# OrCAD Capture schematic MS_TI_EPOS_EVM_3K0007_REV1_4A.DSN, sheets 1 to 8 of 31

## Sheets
1 Pg24: PLAT Test: size C; title: TMDXEVM438X; rev: 1.4A; company: Texas Instruments; note: am438x_ePOS_EVM_3k0007_rev1_4a.dsn; note: ARM MPU BU; note: Final
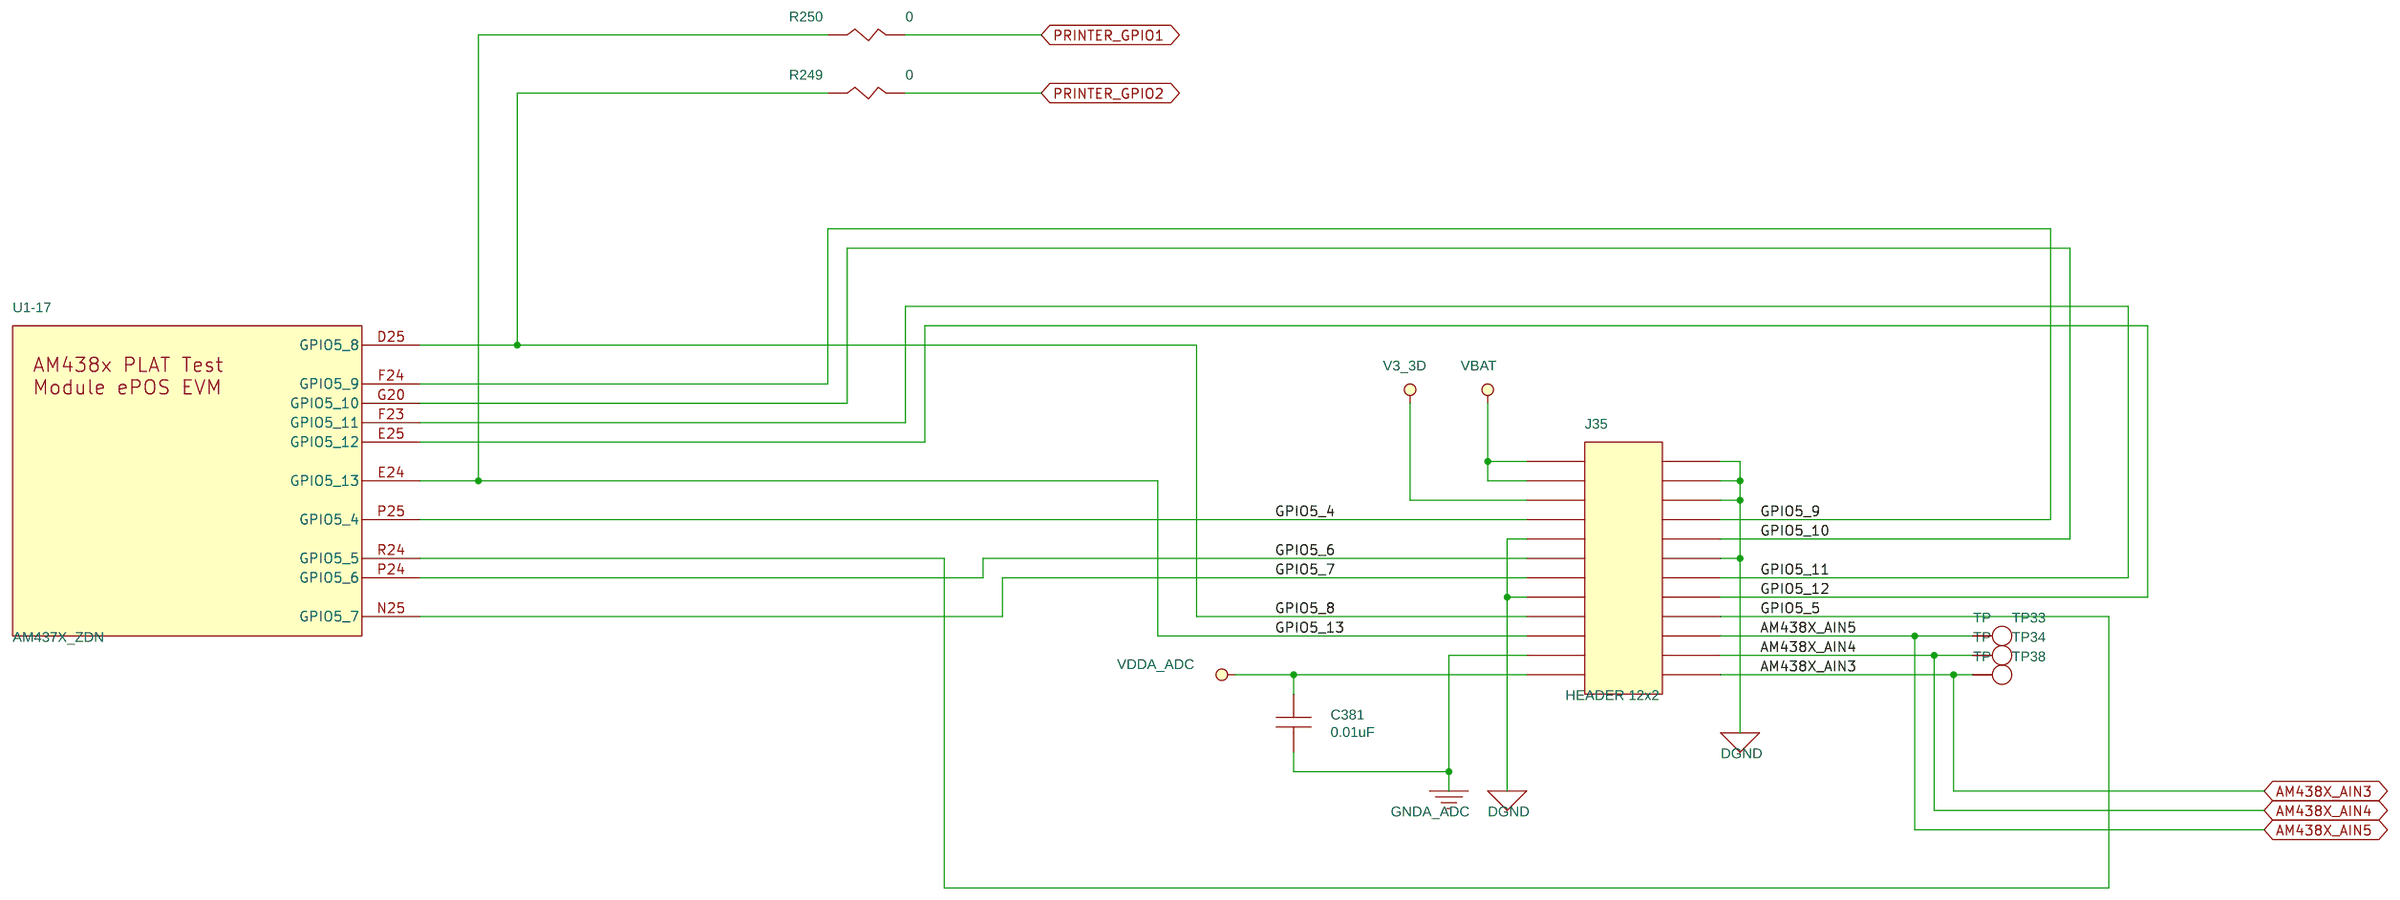
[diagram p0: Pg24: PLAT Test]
2 Pg15: Audio: size C
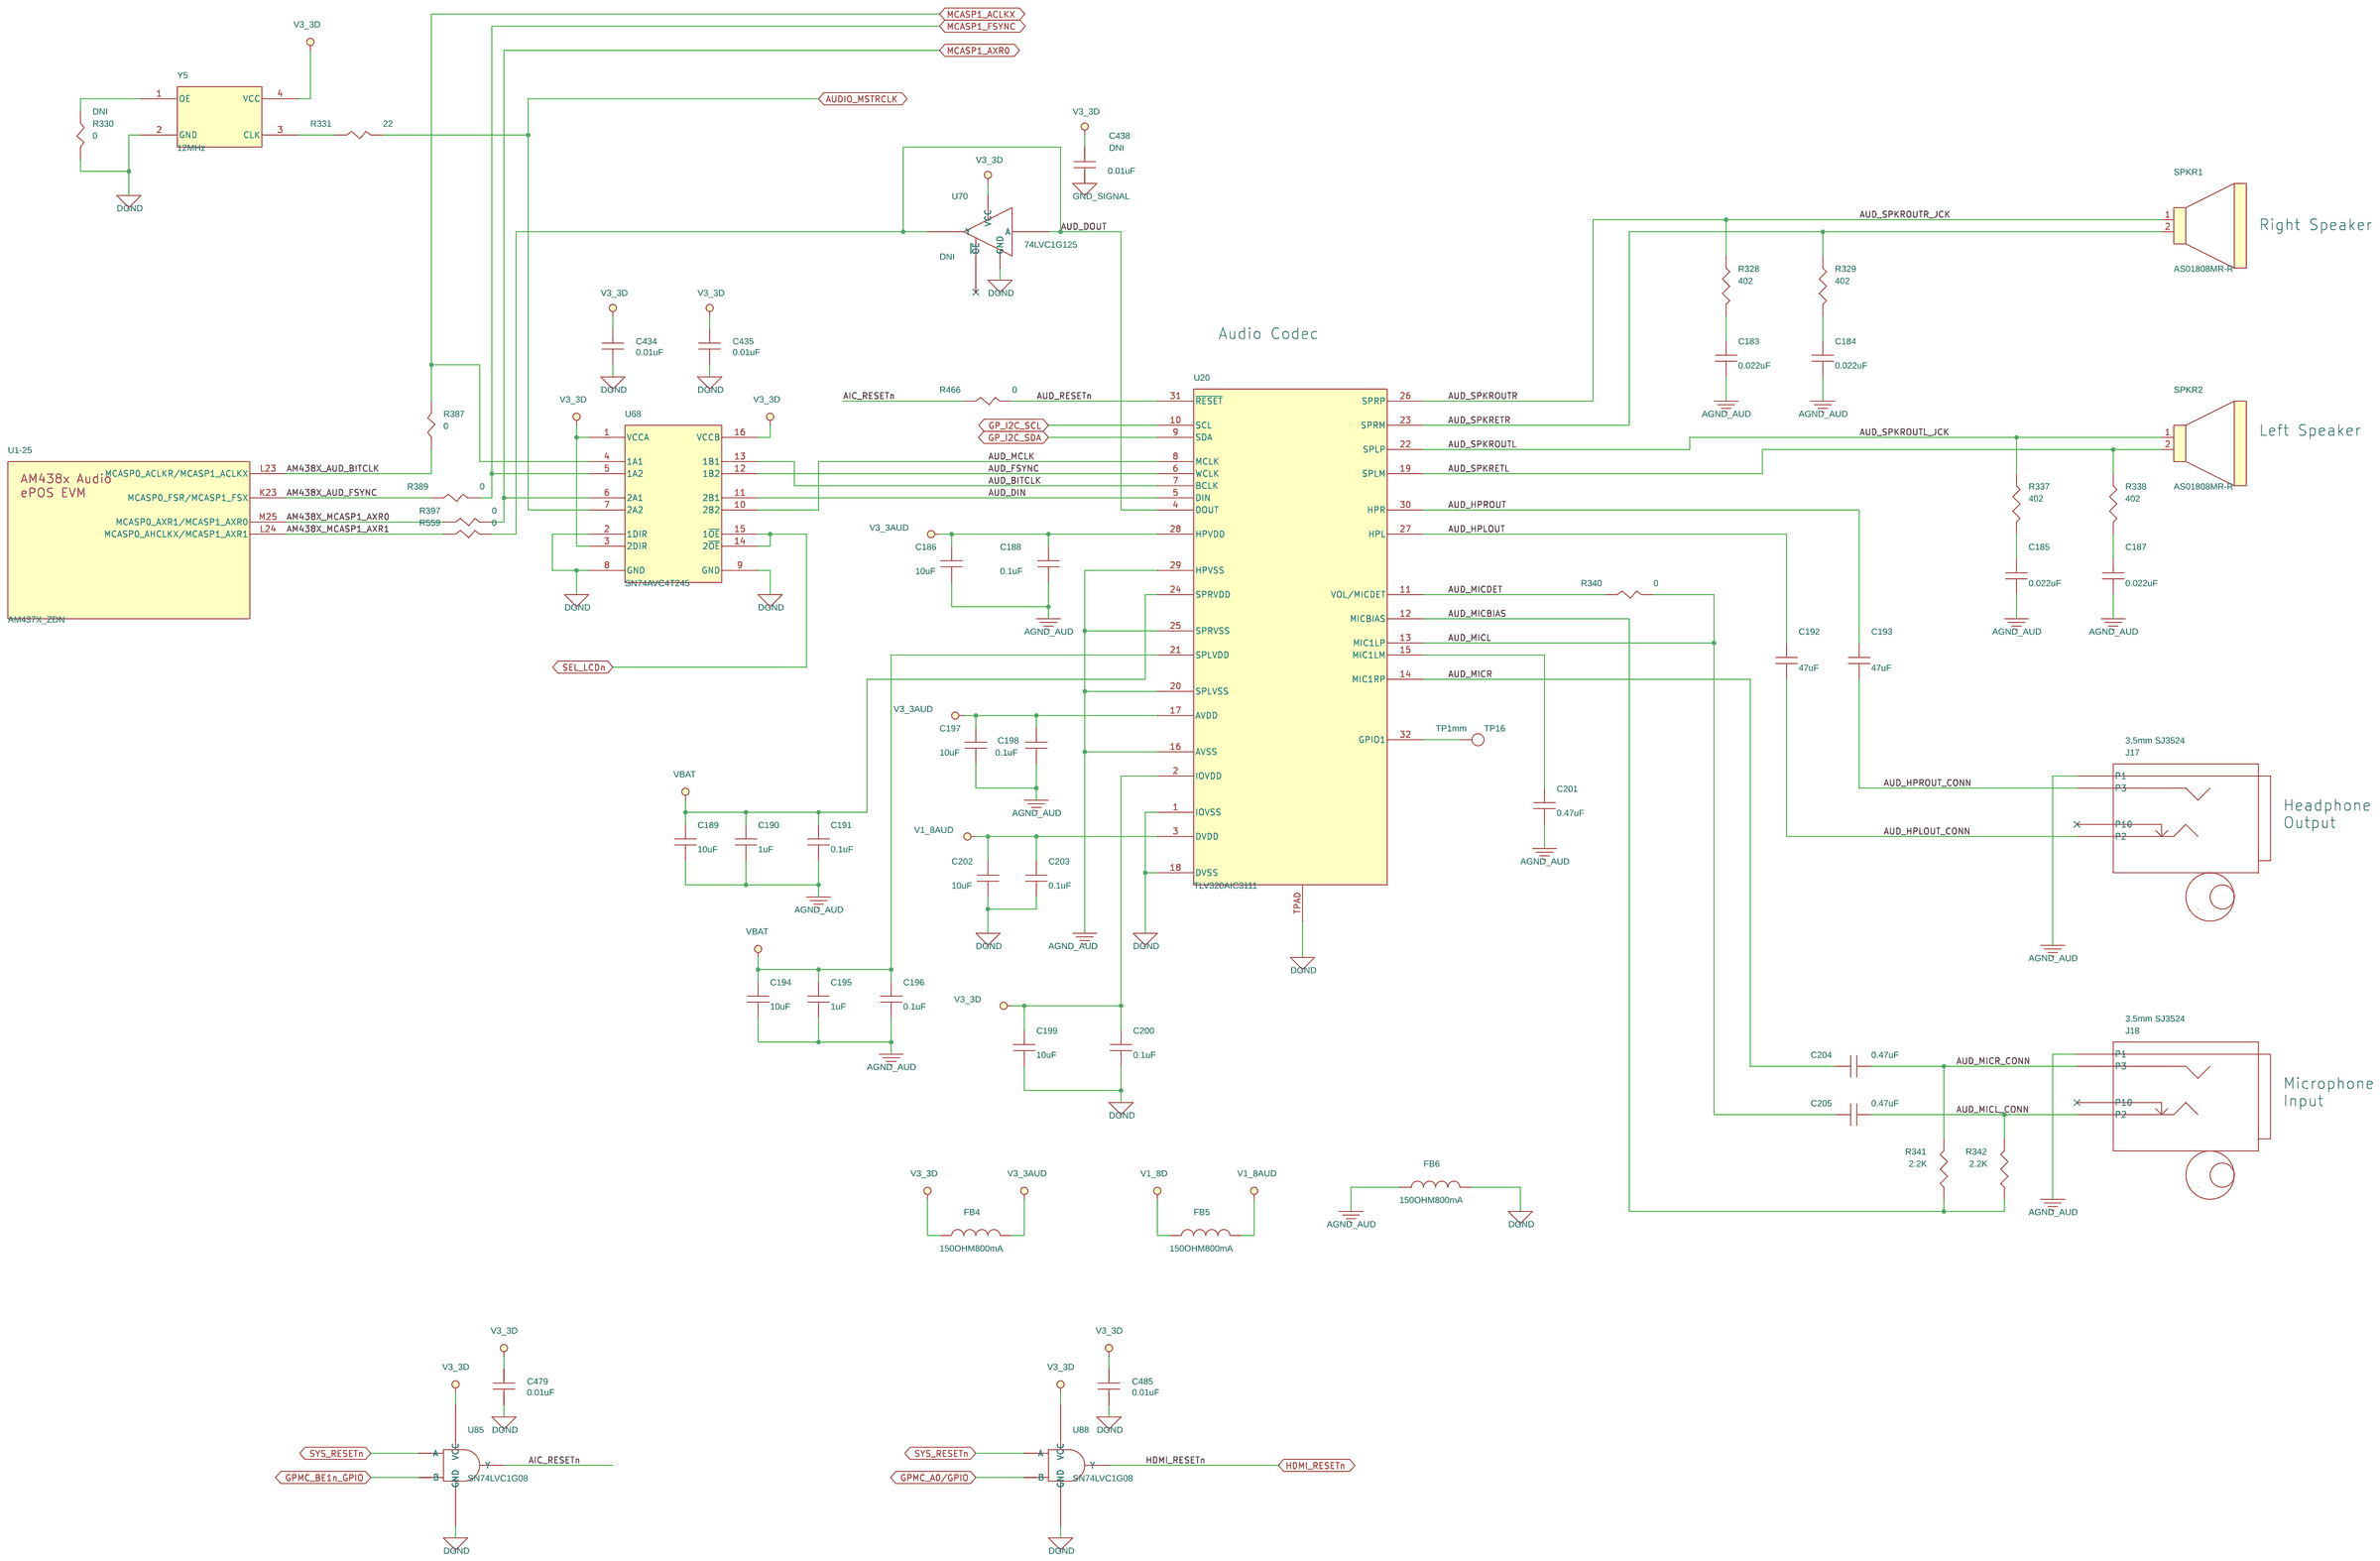
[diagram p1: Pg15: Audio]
3 Pg27: ADC: size C
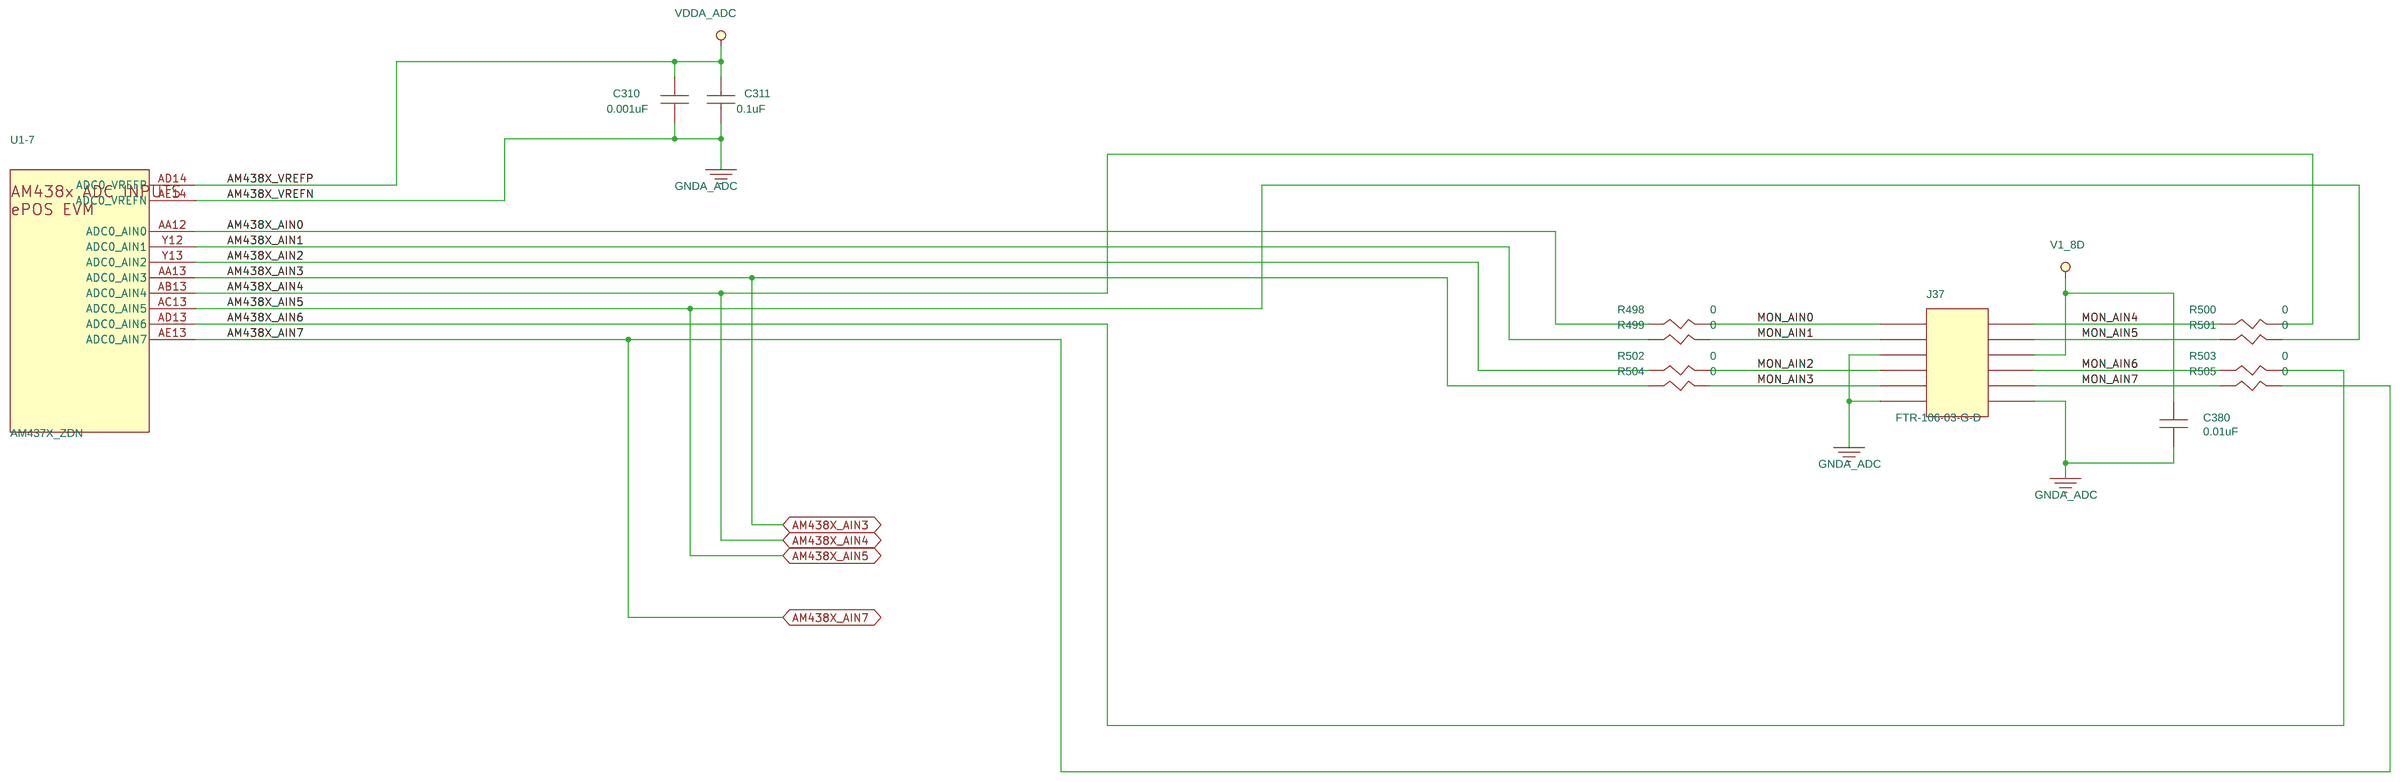
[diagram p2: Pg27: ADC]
4 Pg12: LCD: size C
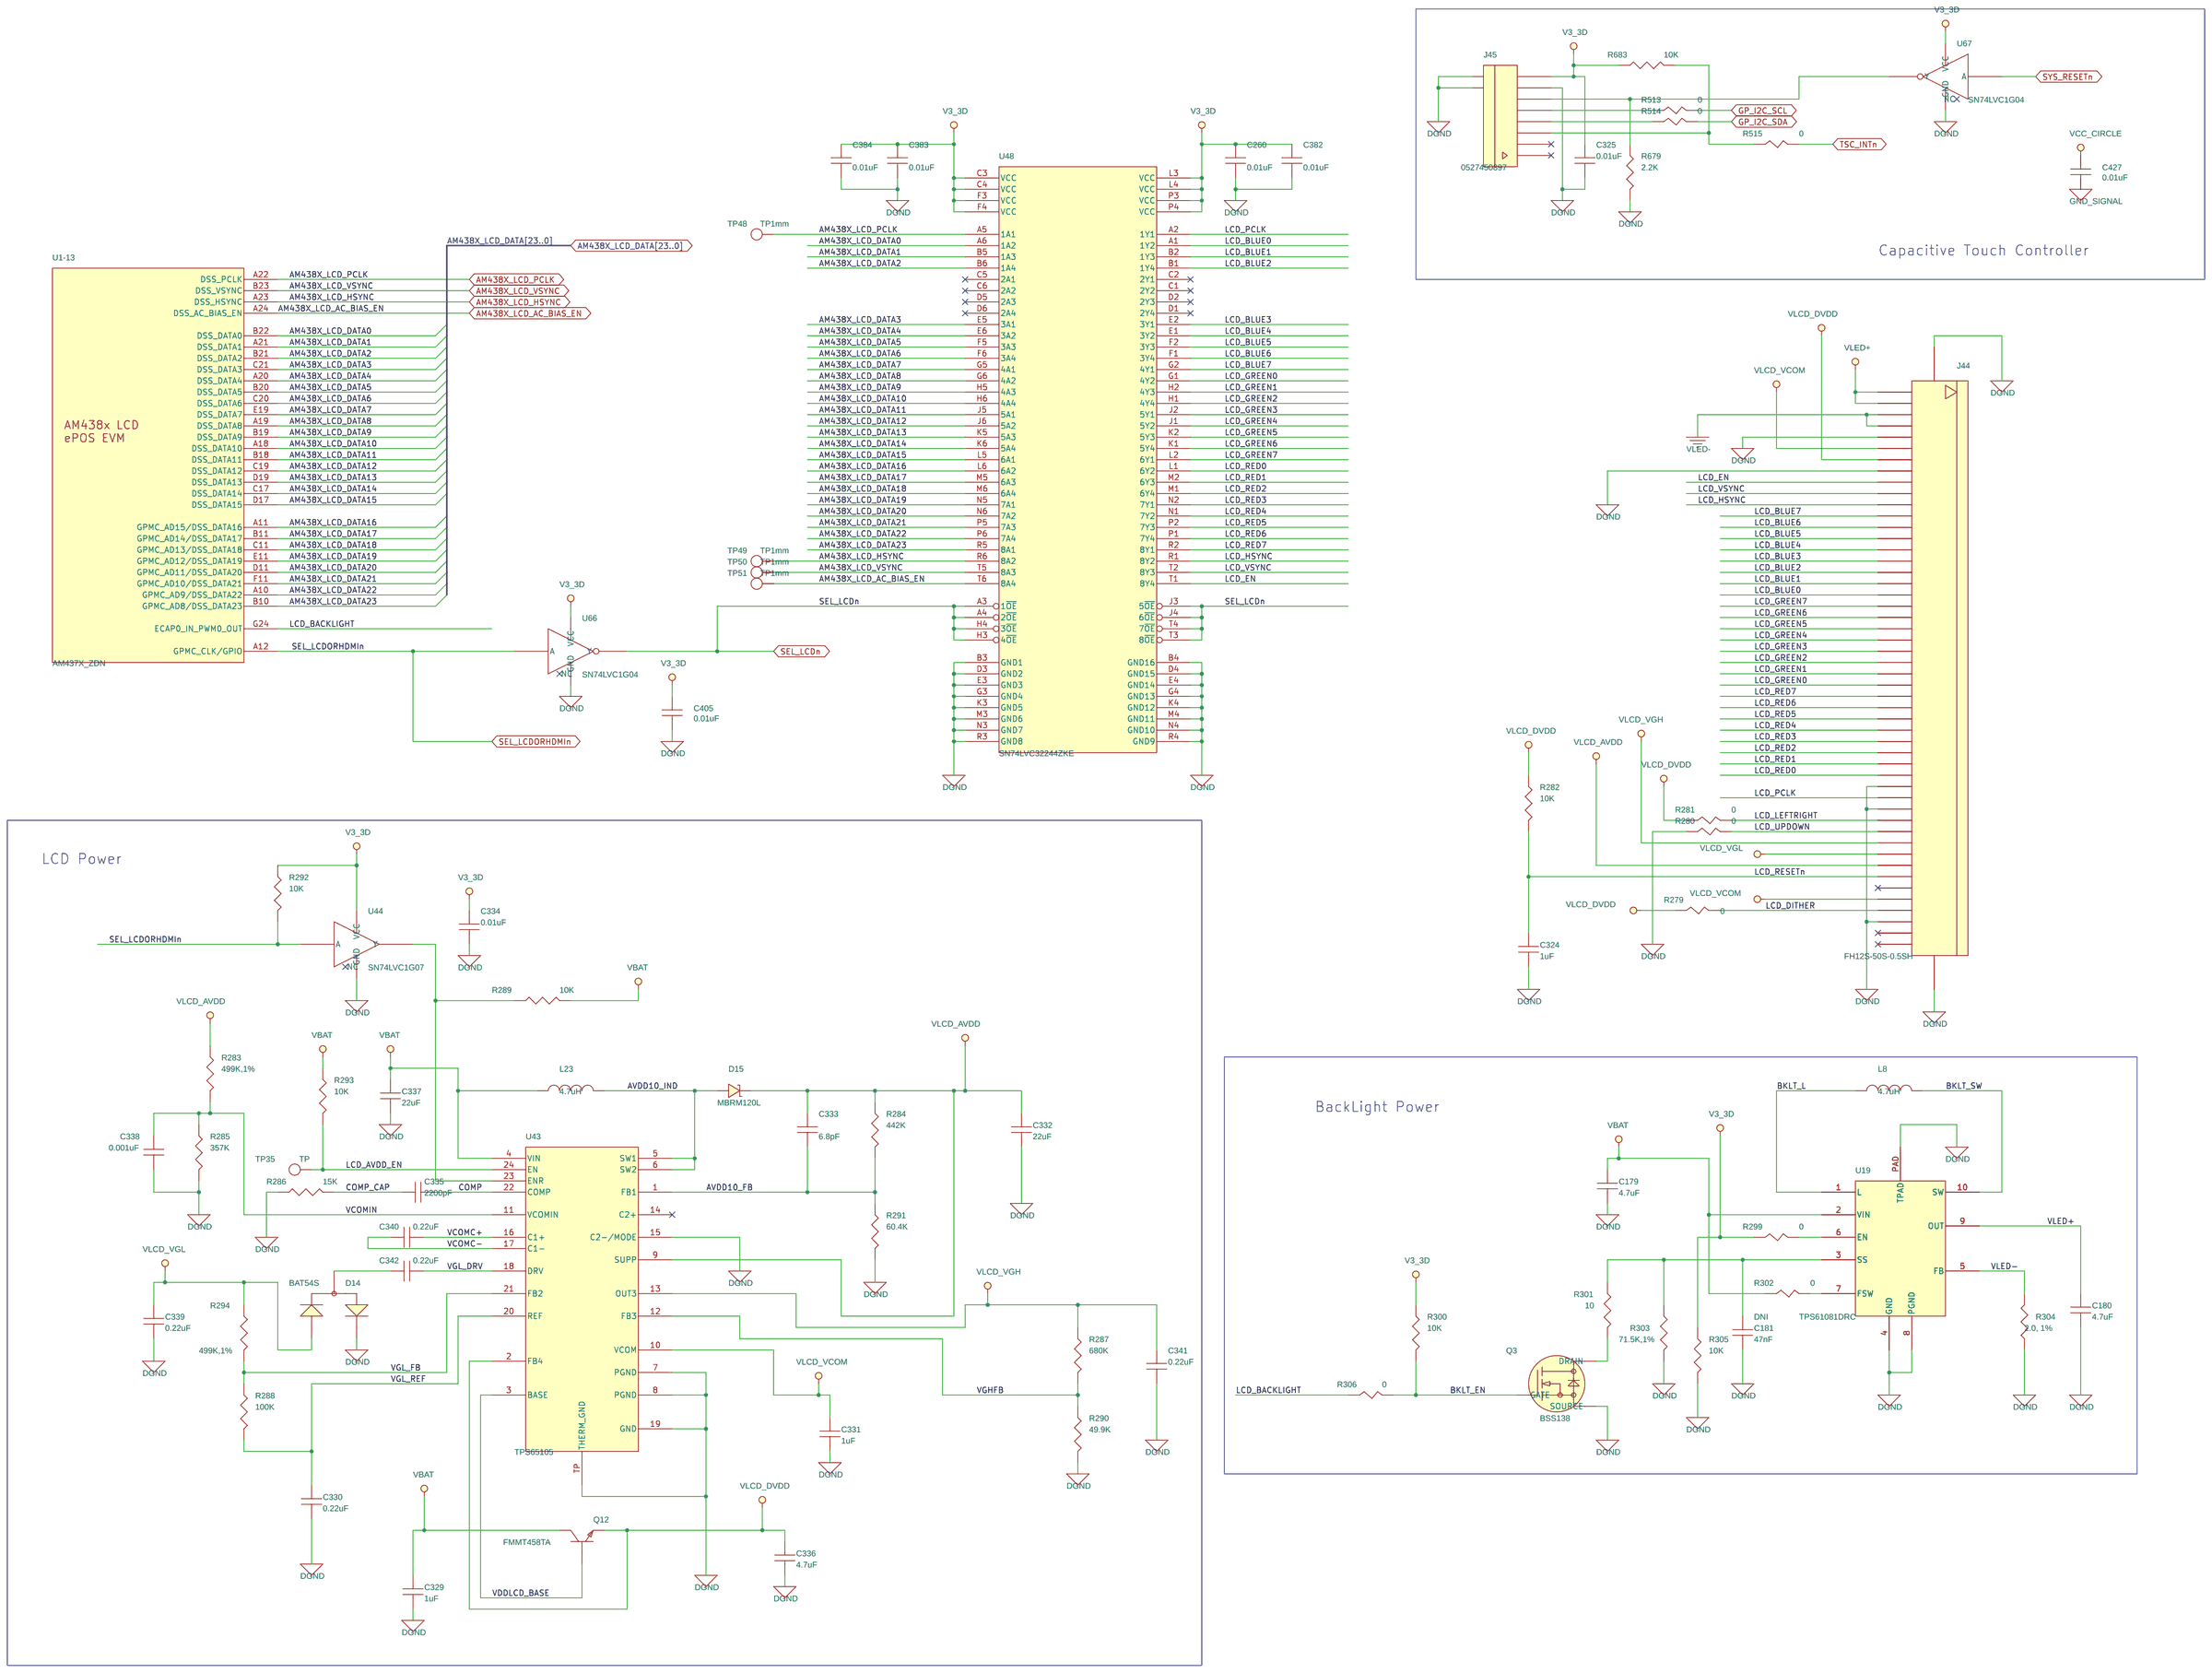
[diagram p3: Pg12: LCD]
5 Pg14: HDMI: size C
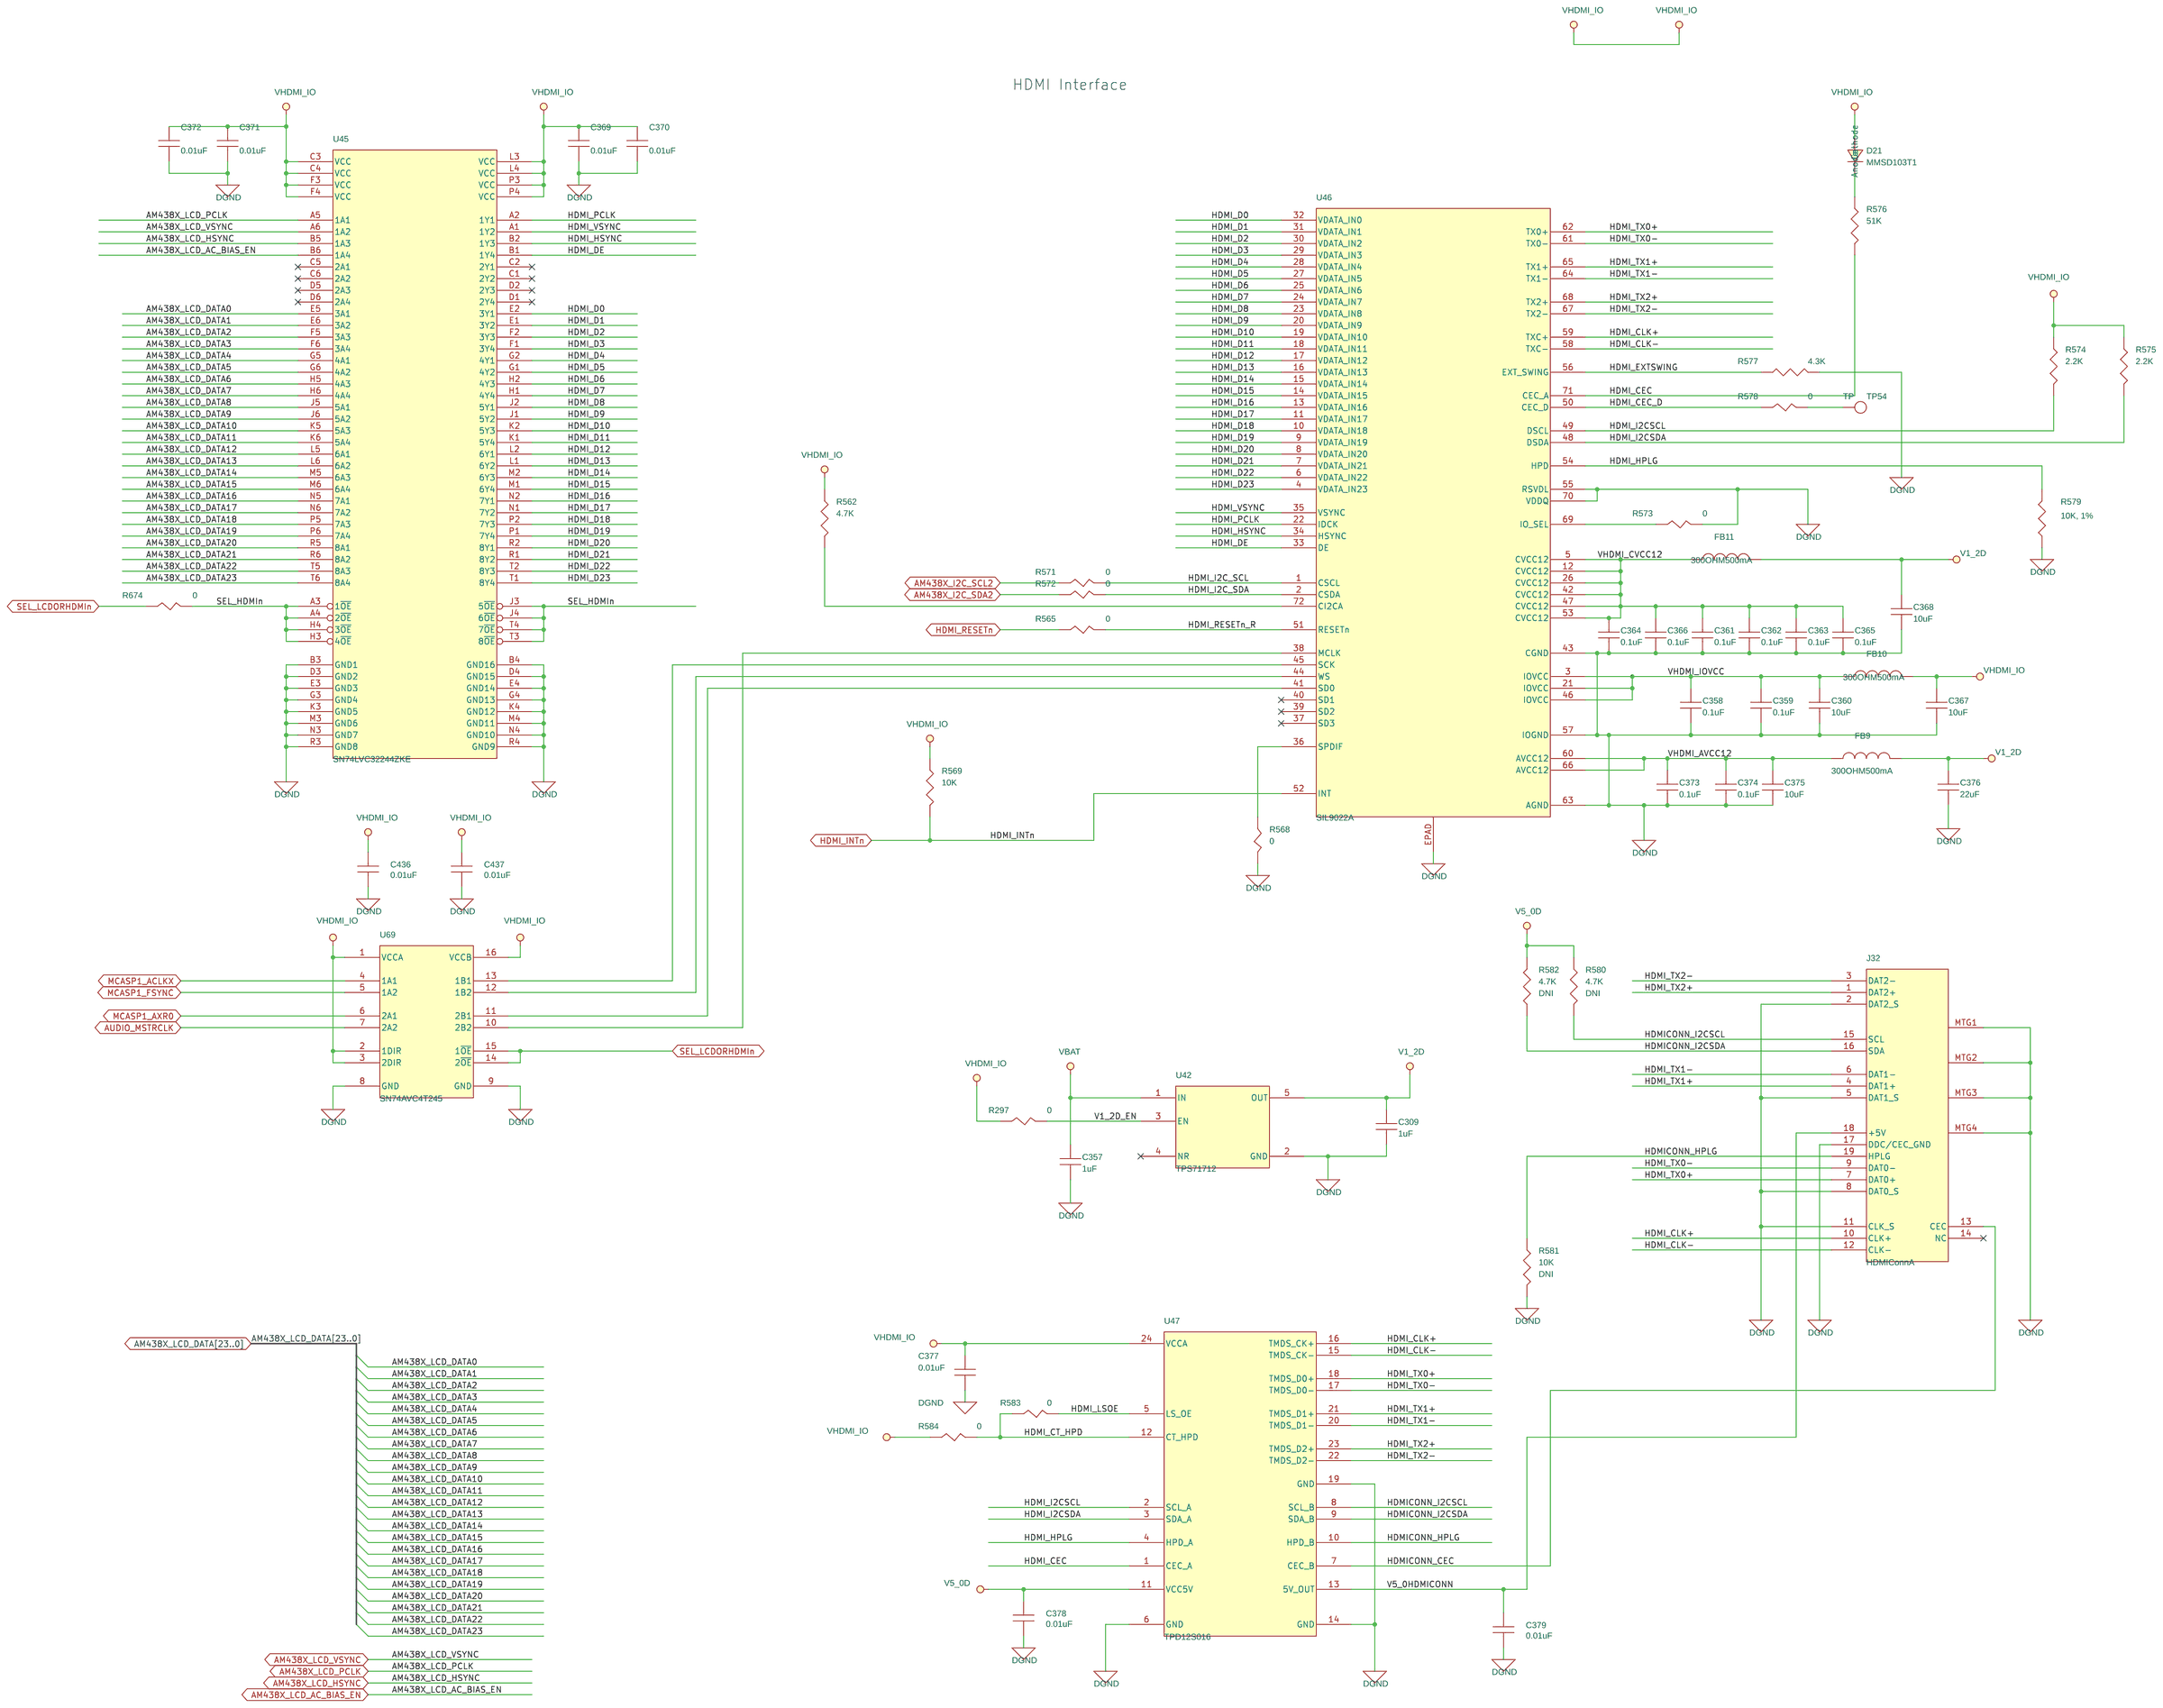
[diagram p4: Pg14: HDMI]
6 Pg25: Mag ADC: size C
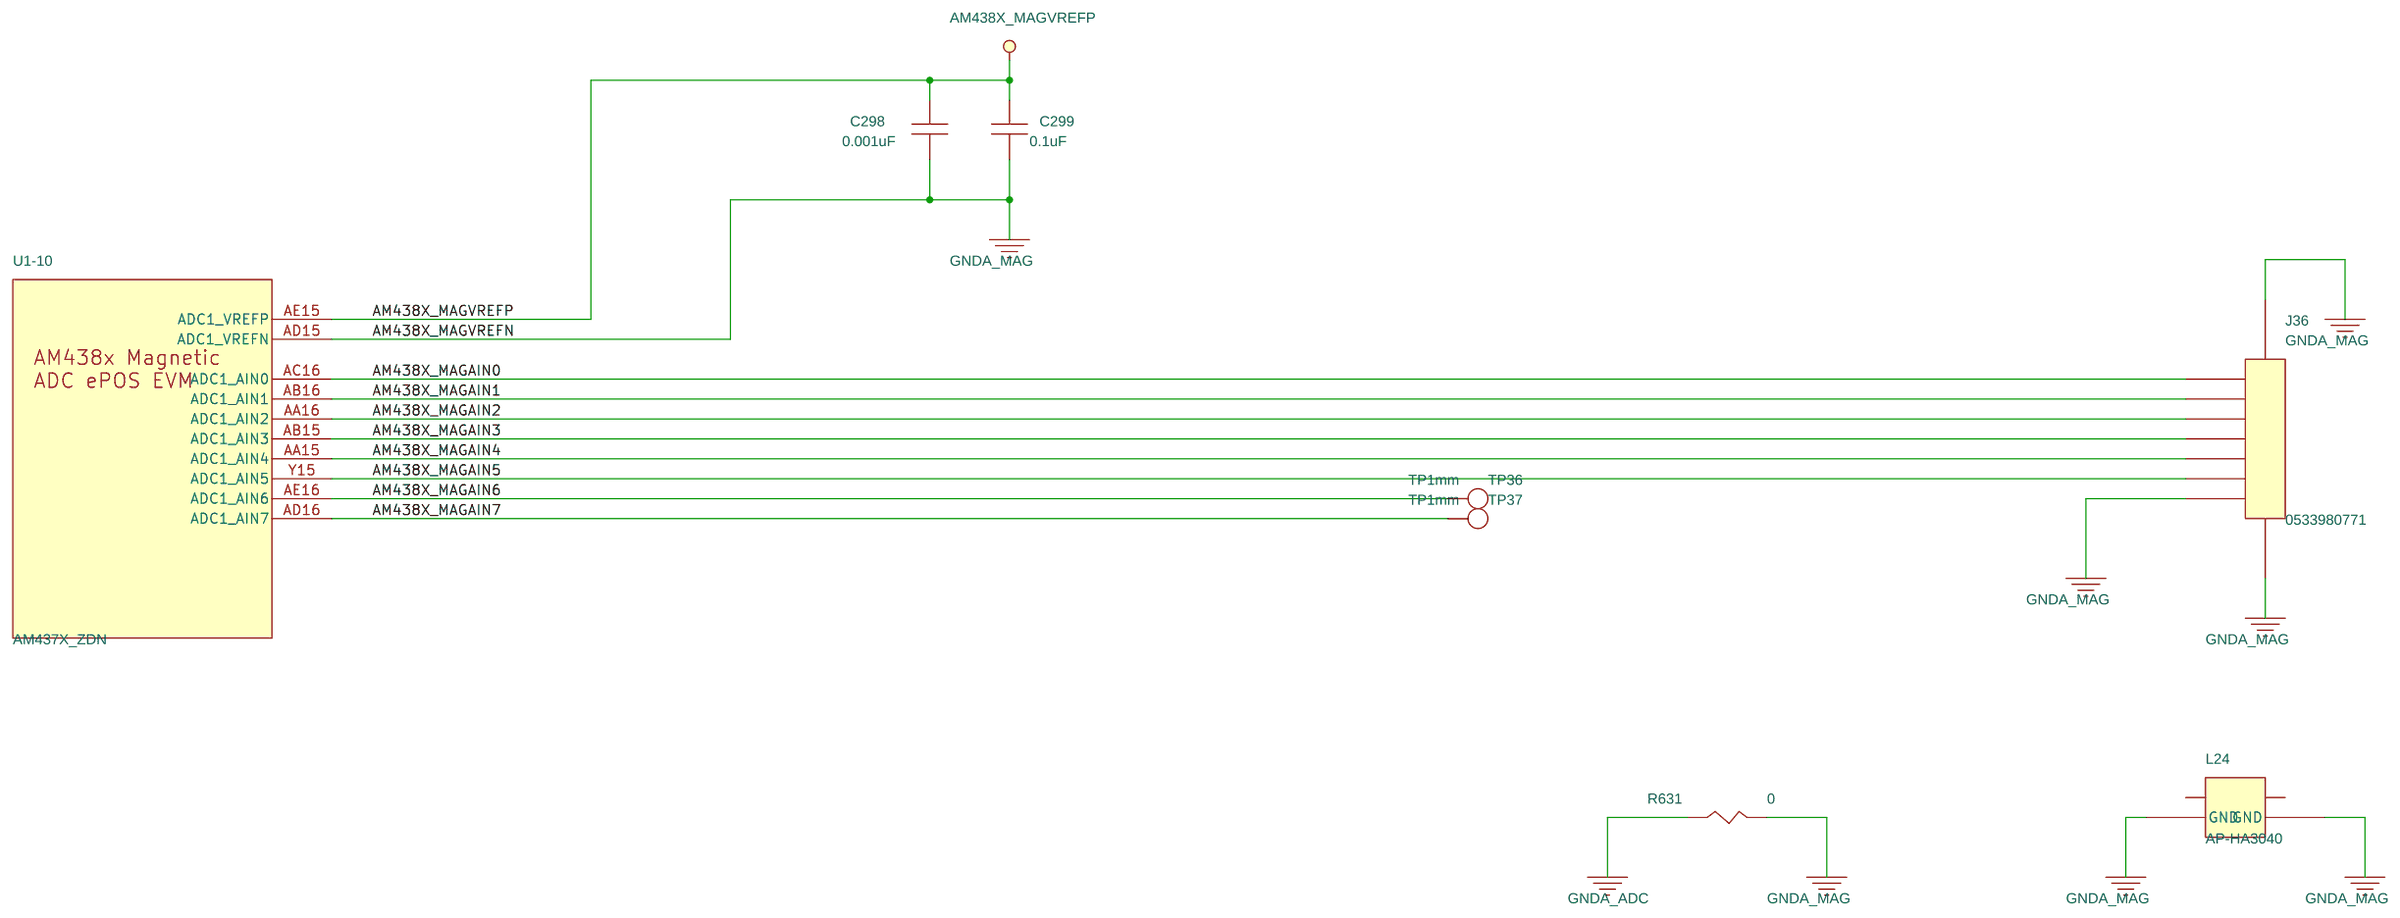
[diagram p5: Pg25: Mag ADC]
7 Pg13: Camera: size C
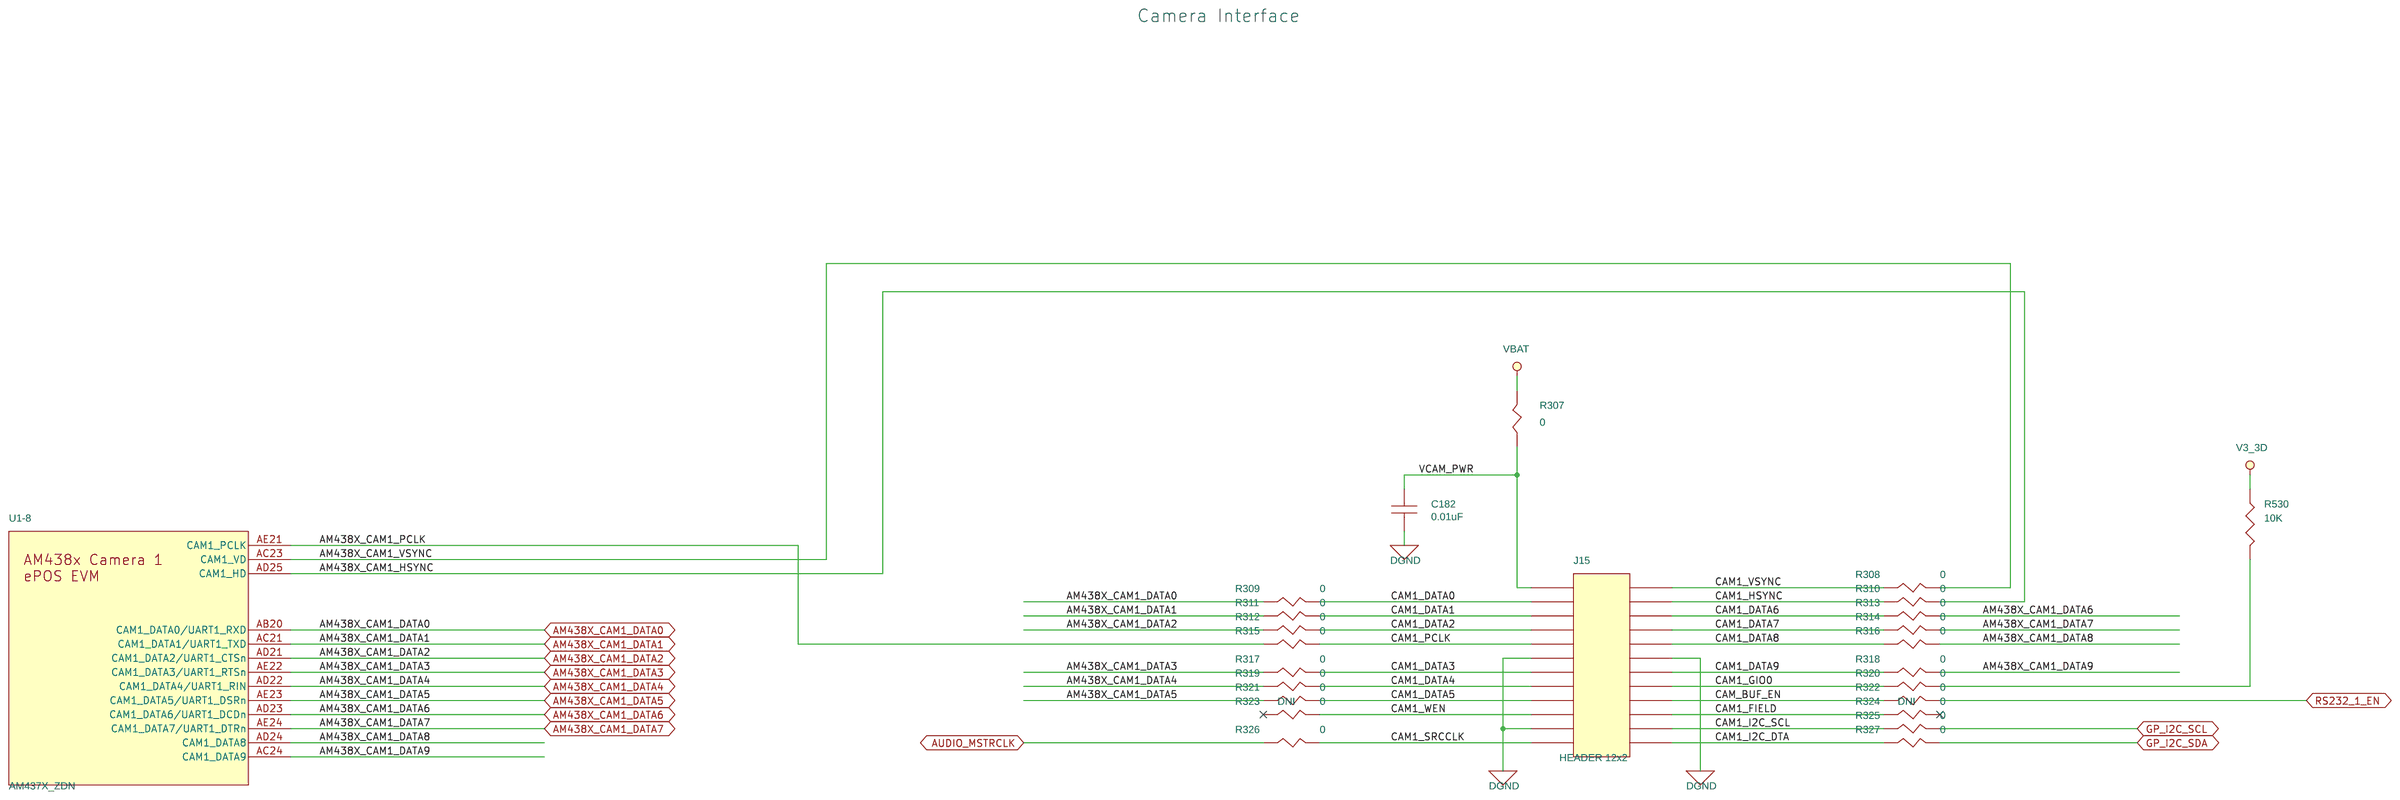
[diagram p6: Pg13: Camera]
8 Pg11: USB JTAG: size C
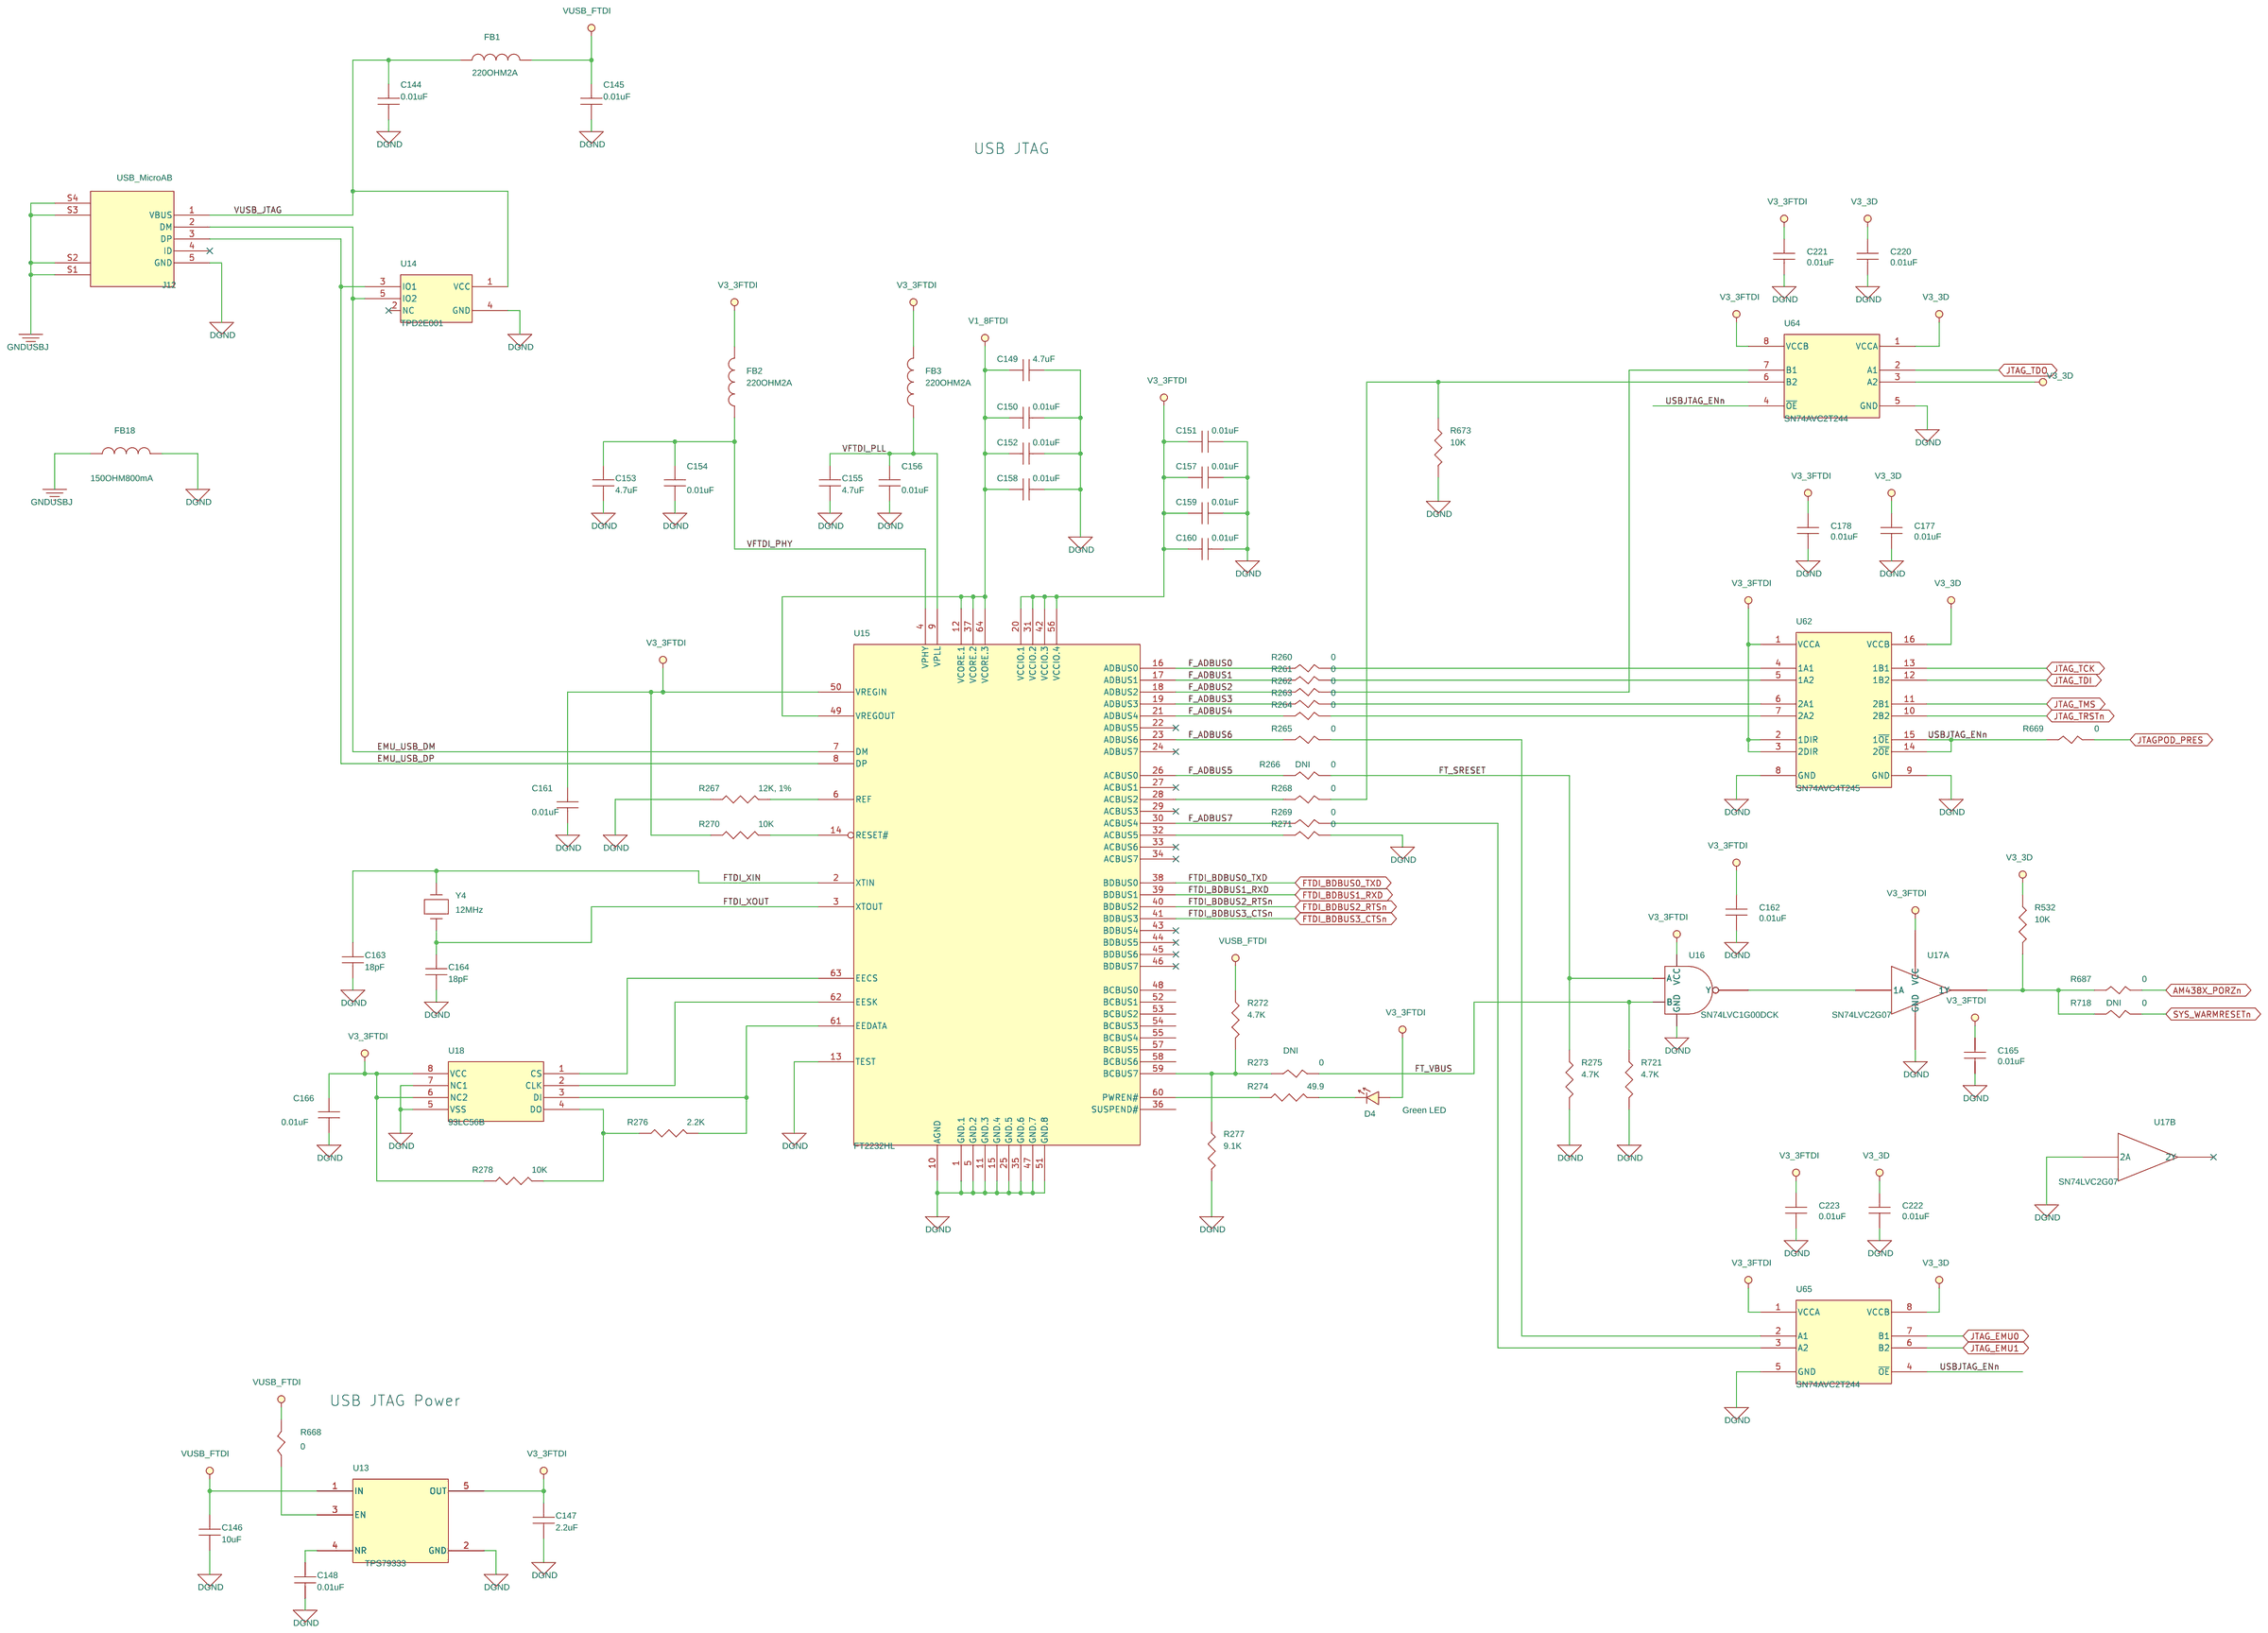
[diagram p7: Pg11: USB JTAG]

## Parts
sheet Pg11: USB JTAG
C144  0.01uF  [SM-7351-CAP-0402]
C145  0.01uF  [SM-7351-CAP-0402]
C146  10uF  [SM-7351-CAP-0805]
C147  2.2uF  [SM-7351-CAP-0805]
C148  0.01uF  [SM-7351-CAP-0402]
C149  4.7uF  [SM-7351-CAP-0603]
C150  0.01uF  [SM-7351-CAP-0402]
C151  0.01uF  [SM-7351-CAP-0402]
C152  0.01uF  [SM-7351-CAP-0402]
C153  4.7uF  [SM-7351-CAP-0603]
C154  0.01uF  [SM-7351-CAP-0402]
C155  4.7uF  [SM-7351-CAP-0603]
C156  0.01uF  [SM-7351-CAP-0402]
C157  0.01uF  [SM-7351-CAP-0402]
C158  0.01uF  [SM-7351-CAP-0402]
C159  0.01uF  [SM-7351-CAP-0402]
C160  0.01uF  [SM-7351-CAP-0402]
C161  0.01uF  [SM-7351-CAP-0402]
C162  0.01uF  [SM-7351-CAP-0402]
C163  18pF  [SM-7351-CAP-0402]
C164  18pF  [SM-7351-CAP-0402]
C165  0.01uF  [SM-7351-CAP-0402]
C166  0.01uF  [SM-7351-CAP-0402]
C177  0.01uF  [SM-7351-CAP-0402]
C178  0.01uF  [SM-7351-CAP-0402]
C220  0.01uF  [SM-7351-CAP-0402]
C221  0.01uF  [SM-7351-CAP-0402]
C222  0.01uF  [SM-7351-CAP-0402]
C223  0.01uF  [SM-7351-CAP-0402]
D4  Green LED  [sm_led_0805]
FB1  220OHM2A  [sm-7351-ind-0603]
FB2  220OHM2A  [sm-7351-ind-0603]
FB3  220OHM2A  [sm-7351-ind-0603]
FB18  150OHM800mA  [sm-7351-ind-0805]
J12  USB_MicroAB  [ZX62-AB-5PA]
R260  0  [SM-7351-RES-0402]
R261  0  [SM-7351-RES-0402]
R262  0  [SM-7351-RES-0402]
R263  0  [SM-7351-RES-0402]
R264  0  [SM-7351-RES-0402]
R265  0  [SM-7351-RES-0402]
R266  0  [SM-7351-RES-0402]
R267  12K, 1%  [SM-7351-RES-0402]
R268  0  [SM-7351-RES-0402]
R269  0  [SM-7351-RES-0402]
R270  10K  [SM-7351-RES-0402]
R271  0  [SM-7351-RES-0402]
R272  4.7K  [SM-7351-RES-0402]
R273  0  [SM-7351-RES-0402]
R274  49.9  [SM-7351-RES-0402]
R275  4.7K  [SM-7351-RES-0402]
R276  2.2K  [sm-7351-res-0402]
R277  9.1K  [SM-7351-RES-0402]
R278  10K  [SM-7351-RES-0402]
R532  10K  [SM-7351-RES-0402]
R668  0  [SM-7351-RES-0402]
R669  0  [SM-7351-RES-0402]
R673  10K  [SM-7351-RES-0402]
R687  0  [SM-7351-RES-0402]
R718  0  [SM-7351-RES-0402]
R721  4.7K  [SM-7351-RES-0402]
U13  TPS79333  [U_5_DBV]
U14  TPD2E001  [U_5_DRL]
U15  FT2232HL  [LQFP64pin]
U16  SN74LVC1G00DCK  [SC70-5-43M]
U17  SN74LVC2G07  [U_6_DCK]  (sections A,B)
U18  93LC56B  [SOIC8_MC]
U62  SN74AVC4T245  [U_16_PW]
U64  SN74AVC2T244  [son2x1-8-16m]
U65  SN74AVC2T244  [son2x1-8-16m]
Y4  12MHz  [SM_OSC_ABM3]
sheet Pg12: LCD
C179  4.7uF  [SM-7351-CAP-0603]
C180  4.7uF  [SM-7351-CAP-0603]
C181  47nF  [SM-7351-CAP-0402]
C260  0.01uF  [SM-7351-CAP-0402]
C324  1uF  [SM-7351-CAP-0402]
C325  0.01uF  [SM-7351-CAP-0402]
C329  1uF  [SM-7351-CAP-0402]
C330  0.22uF  [SM-7351-CAP-0603]
C331  1uF  [SM-7351-CAP-0402]
C332  22uF  [SM-7351-CAP-0805]
C333  6.8pF  [SM-7351-CAP-0402]
C334  0.01uF  [SM-7351-CAP-0402]
C335  2200pF  [SM-7351-CAP-0402]
C336  4.7uF  [SM-7351-CAP-0603]
C337  22uF  [SM-7351-CAP-0805]
C338  0.001uF  [SM-7351-CAP-0402]
C339  0.22uF  [SM-7351-CAP-0603]
C340  0.22uF  [SM-7351-CAP-0603]
C341  0.22uF  [SM-7351-CAP-0603]
C342  0.22uF  [SM-7351-CAP-0603]
C382  0.01uF  [SM-7351-CAP-0402]
C383  0.01uF  [SM-7351-CAP-0402]
C384  0.01uF  [SM-7351-CAP-0402]
C405  0.01uF  [SM-7351-CAP-0402]
C427  0.01uF  [SM-7351-CAP-0402]
D14  BAT54S  [SM_SOT323-3]
D15  MBRM120L  [SM_DIO_CASE_457-04]
J44  FH12S-50S-0.5SH  [cnfh12s-50s-05sh]
J45  0527450897  [CN527450-897]
L8  4.7uH  [vlcf5020t]
L23  4.7uH  [sm_ind_lqh32cn]
Q3  BSS138  [SOT23-3]
Q12  FMMT458TA  [sm_sot23_bce]
R279  0  [SM-7351-RES-0402]
R280  0  [SM-7351-RES-0402]
R281  0  [SM-7351-RES-0402]
R282  10K  [SM-7351-RES-0402]
R283  499K,1%  [SM-7351-RES-0402]
R284  442K  [SM-7351-RES-0402]
R285  357K  [SM-7351-RES-0402]
R286  15K  [SM-7351-RES-0402]
R287  680K  [SM-7351-RES-0402]
R288  100K  [SM-7351-RES-0402]
R289  10K  [SM-7351-RES-0402]
R290  49.9K  [SM-7351-RES-0402]
R291  60.4K  [SM-7351-RES-0402]
R292  10K  [SM-7351-RES-0402]
R293  10K  [SM-7351-RES-0402]
R294  499K,1%  [SM-7351-RES-0402]
R299  0  [SM-7351-RES-0402]
R300  10K  [SM-7351-RES-0402]
R301  10  [SM-7351-RES-0402]
R302  0  [SM-7351-RES-0402]
R303  71.5K,1%  [SM-7351-RES-0402]
R304  2.0, 1%  [SM-7351-RES-0603]
R305  10K  [SM-7351-RES-0402]
R306  0  [SM-7351-RES-0402]
R513  0  [SM-7351-RES-0402]
R514  0  [SM-7351-RES-0402]
R515  0  [SM-7351-RES-0402]
R679  2.2K  [sm-7351-res-0402]
R683  10K  [SM-7351-RES-0402]
TP35  TP  [TH_TP_5002]
TP48  TP1mm  [tp_smd1mmcircle]
TP49  TP1mm  [tp_smd1mmcircle]
TP50  TP1mm  [tp_smd1mmcircle]
TP51  TP1mm  [tp_smd1mmcircle]
U19  TPS61081DRC  [u_10_drc]
U43  TPS65105  [u_24_pw]
U44  SN74LVC1G07  [SC70-5-43M]
U48  SN74LVC32244ZKE  [bga13x5-96]
U66  SN74LVC1G04  [SC70-5-43M]
U67  SN74LVC1G04  [SC70-5-43M]
sheet Pg13: Camera
C182  0.01uF  [SM-7351-CAP-0402]
J15  HEADER 12x2  [hdr2x12]
R307  0  [SM-7351-RES-0402]
R308  0  [SM-7351-RES-0402]
R309  0  [SM-7351-RES-0402]
R310  0  [SM-7351-RES-0402]
R311  0  [SM-7351-RES-0402]
R312  0  [SM-7351-RES-0402]
R313  0  [SM-7351-RES-0402]
R314  0  [SM-7351-RES-0402]
R315  0  [SM-7351-RES-0402]
R316  0  [SM-7351-RES-0402]
R317  0  [SM-7351-RES-0402]
R318  0  [SM-7351-RES-0402]
R319  0  [SM-7351-RES-0402]
R320  0  [SM-7351-RES-0402]
R321  0  [SM-7351-RES-0402]
R322  0  [SM-7351-RES-0402]
R323  0  [SM-7351-RES-0402]
R324  0  [SM-7351-RES-0402]
R325  0  [SM-7351-RES-0402]
R326  0  [SM-7351-RES-0402]
R327  0  [SM-7351-RES-0402]
R530  10K  [SM-7351-RES-0402]
sheet Pg14: HDMI
C309  1uF  [SM-7351-CAP-0402]
C357  1uF  [SM-7351-CAP-0402]
C358  0.1uF  [SM-7351-CAP-0402]
C359  0.1uF  [SM-7351-CAP-0402]
C360  10uF  [SM-7351-CAP-0805]
C361  0.1uF  [SM-7351-CAP-0402]
C362  0.1uF  [SM-7351-CAP-0402]
C363  0.1uF  [SM-7351-CAP-0402]
C364  0.1uF  [SM-7351-CAP-0402]
C365  0.1uF  [SM-7351-CAP-0402]
C366  0.1uF  [SM-7351-CAP-0402]
C367  10uF  [SM-7351-CAP-0805]
C368  10uF  [SM-7351-CAP-0805]
C369  0.01uF  [SM-7351-CAP-0402]
C370  0.01uF  [SM-7351-CAP-0402]
C371  0.01uF  [SM-7351-CAP-0402]
C372  0.01uF  [SM-7351-CAP-0402]
C373  0.1uF  [SM-7351-CAP-0402]
C374  0.1uF  [SM-7351-CAP-0402]
C375  10uF  [SM-7351-CAP-0805]
C376  22uF  [SM-7351-CAP-0805]
C377  0.01uF  [SM-7351-CAP-0402]
C378  0.01uF  [SM-7351-CAP-0402]
C379  0.01uF  [SM-7351-CAP-0402]
C436  0.01uF  [SM-7351-CAP-0402]
C437  0.01uF  [SM-7351-CAP-0402]
D21  MMSD103T1  [sod-123]
FB9  300OHM500mA  [sm-7351-ind-0603]
FB10  300OHM500mA  [sm-7351-ind-0603]
FB11  300OHM500mA  [sm-7351-ind-0603]
J32  HDMIConnA  [smd_hdmia_ra]
R297  0  [SM-7351-RES-0402]
R562  4.7K  [SM-7351-RES-0402]
R565  0  [SM-7351-RES-0402]
R568  0  [SM-7351-RES-0402]
R569  10K  [SM-7351-RES-0402]
R571  0  [SM-7351-RES-0402]
R572  0  [SM-7351-RES-0402]
R573  0  [SM-7351-RES-0402]
R574  2.2K  [sm-7351-res-0402]
R575  2.2K  [sm-7351-res-0402]
R576  51K  [SM-7351-RES-0402]
R577  4.3K  [SM-7351-RES-0402]
R578  0  [SM-7351-RES-0402]
R579  10K, 1%  [SM-7351-RES-0402]
R580  4.7K  [SM-7351-RES-0402]
R581  10K  [SM-7351-RES-0402]
R582  4.7K  [SM-7351-RES-0402]
R583  0  [SM-7351-RES-0402]
R584  0  [SM-7351-RES-0402]
R674  0  [SM-7351-RES-0402]
TP54  TP  [TH_TP_5002]
U42  TPS71712  [smdsc70-5]
U45  SN74LVC32244ZKE  [bga13x5-96]
U46  SIL9022A  [QFN_72]
U47  TPD12S016  [pw_24pin_tssop]
U69  SN74AVC4T245  [U_16_PW]
sheet Pg15: Audio
C183  0.022uF  [SM-7351-CAP-0402]
C184  0.022uF  [SM-7351-CAP-0402]
C185  0.022uF  [SM-7351-CAP-0402]
C186  10uF  [SM-7351-CAP-0805]
C187  0.022uF  [SM-7351-CAP-0402]
C188  0.1uF  [SM-7351-CAP-0402]
C189  10uF  [SM-7351-CAP-0805]
C190  1uF  [SM-7351-CAP-0603]
C191  0.1uF  [SM-7351-CAP-0402]
C192  47uF  [SM-7351-CAP-1206]
C193  47uF  [SM-7351-CAP-1206]
C194  10uF  [SM-7351-CAP-0805]
C195  1uF  [SM-7351-CAP-0603]
C196  0.1uF  [SM-7351-CAP-0402]
C197  10uF  [SM-7351-CAP-0805]
C198  0.1uF  [SM-7351-CAP-0402]
C199  10uF  [SM-7351-CAP-0805]
C200  0.1uF  [SM-7351-CAP-0402]
C201  0.47uF  [SM-7351-CAP-0402]
C202  10uF  [SM-7351-CAP-0805]
C203  0.1uF  [SM-7351-CAP-0402]
C204  0.47uF  [SM-7351-CAP-0402]
C205  0.47uF  [SM-7351-CAP-0402]
C434  0.01uF  [SM-7351-CAP-0402]
C435  0.01uF  [SM-7351-CAP-0402]
C438  0.01uF  [SM-7351-CAP-0402]
C479  0.01uF  [SM-7351-CAP-0402]
C485  0.01uF  [SM-7351-CAP-0402]
FB4  150OHM800mA  [sm-7351-ind-0805]
FB5  150OHM800mA  [sm-7351-ind-0805]
FB6  150OHM800mA  [sm-7351-ind-0805]
J17  3.5mm SJ3524  [sj3524smt4pin]
J18  3.5mm SJ3524  [sj3524smt4pin]
R328  402  [SM-7351-RES-0603]
R329  402  [SM-7351-RES-0603]
R330  0  [SM-7351-RES-0402]
R331  22  [SM-7351-RES-0402]
R337  402  [SM-7351-RES-0603]
R338  402  [SM-7351-RES-0603]
R340  0  [SM-7351-RES-0402]
R341  2.2K  [sm-7351-res-0402]
R342  2.2K  [sm-7351-res-0402]
R387  0  [SM-7351-RES-0402]
R389  0  [SM-7351-RES-0402]
R397  0  [SM-7351-RES-0402]
R466  0  [SM-7351-RES-0402]
R559  0  [SM-7351-RES-0402]
SPKR1  AS01808MR-R  [th_as01808mr-r_cust]
SPKR2  AS01808MR-R  [th_as01808mr-r_cust]
TP16  TP1mm  [tp_smd1mmcircle]
U20  TLV320AIC3111  [qfn5x5-32ti-39m]
U68  SN74AVC4T245  [U_16_PW]
U70  74LVC1G125  [U_5_DCK]
U85  SN74LVC1G08  [sm-so-sc70-5]
U88  SN74LVC1G08  [sm-so-sc70-5]
Y5  12MHz  [ecs_smd3_2x5mm]
sheet Pg24: PLAT Test
C381  0.01uF  [SM-7351-CAP-0402]
J35  HEADER 12x2  [hdr2x12]
R249  0  [SM-7351-RES-0402]
R250  0  [SM-7351-RES-0402]
TP33  TP  [TH_TP_5002]
TP34  TP  [TH_TP_5002]
TP38  TP  [TH_TP_5002]
sheet Pg25: Mag ADC
C298  0.001uF  [SM-7351-CAP-0402]
C299  0.1uF  [SM-7351-CAP-0402]
J36  0533980771  [CNSD-0533980771]
L24  AP-HA3040  [AP-HA3040-MSR]
R631  0  [SM-7351-RES-0402]
TP36  TP1mm  [tp_smd1mmcircle]
TP37  TP1mm  [tp_smd1mmcircle]
sheet Pg26: Keypad/LED's
U1  AM437X_ZDN  [AM437X_ZDN]  (sections -1,-10,-11,-12,-13,-14,-15,-16,-17,-18,-19,-2,-20,-21,-22,-23,-24,-25,-26,-27,-3,-4,-5,-6,-7,-8,-9)
sheet Pg27: ADC
C310  0.001uF  [SM-7351-CAP-0402]
C311  0.1uF  [SM-7351-CAP-0402]
C380  0.01uF  [SM-7351-CAP-0402]
J37  FTR-106-03-G-D  [ftr-106-53-g-d-06]
R498  0  [SM-7351-RES-0402]
R499  0  [SM-7351-RES-0402]
R500  0  [SM-7351-RES-0402]
R501  0  [SM-7351-RES-0402]
R502  0  [SM-7351-RES-0402]
R503  0  [SM-7351-RES-0402]
R504  0  [SM-7351-RES-0402]
R505  0  [SM-7351-RES-0402]

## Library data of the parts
C144 C145 C148 C150-C152 C154 C156-C162 C165 C166 C177 C178 C182 C220-C223 C260 C325 C334 C369-C372 C377-C384 C405 C427 C434-C437 C479 C485 = 1C_0.01uFCapacitor16V10%0402: Cost100: 0; Cost10K: 0.01; Mistral Part No: 120009030032-R
C146 C186 C189 C194 C197 C199 C202 C360 C367 C368 C375 = 1C_10uFCapacitor16V10%0805: Cost10K: 0.04; Mistral Part No: 120011040011-R
C147 = 1C_2.2uFCapacitor35V20%smd0805: Cost10K: 0.04; MfrNum: C2012X7R1V225M125AB; Mistral Part No: M120016080004
C149 C153 C155 C179 C180 C336 = 1C_4.7uFCapacitor16V10%0603: Cost100: 0.01; Cost10K: 0; Mistral Part No: 120011050004-R
C163 C164 = 1C_18pFCapacitor16V10%0402: Cost100: 0.02; Cost10K: 0; MfrNum: CGA2B2C0G1H180J050BA; Mistral Part No: 120014050009-R
D4 = 1F_LED_Green: Cost100: 0.08; Cost10K: 0.03; Mistral Part No: 130014050065-R
FB1-FB3 = 1L_FerriteBead_220ohm2A: Cost100: 0.06; Cost10K: 0.04; MfrNum: MPZ1608S221ATA00; Mistral Part No: 130009030553
FB4-FB6 FB18 = 1L_FerBead_180ohm200mA: Cost100: 0.06; Cost10K: 0.04; Mistral Part No: 130014050062-R
J12 = 2C_MicroUSBAB: MfrNum: ZX62-AB-5PA(31); Mistral Part No: 150010120015-R
R249 R250 R260-R265 R268 R269 R271 R279-R281 R297 R299 R302 R306-R322 R325-R327 R340 R387 R389 R397 R466 R498-R505 R513-R515 R559 R565 R568 R571-R573 R578 R583 R584 R631 R668 R669 R674 R687 = 1R_ZeroOhmResistor1_16W0402: Mistral Part No: 110014100008-R
R266 R273 R323 R324 R330 R718 = 1R_ZeroOhmResistor1_16W0402: Loading: DNI; Mistral Part No: 110014100008-R
R267 = 1R_12Kohm1_16W1%SMD0402: Cost10K: 0; Mistral Part No: M110016080004
R270 R278 R282 R289 R292 R293 R300 R305 R530 R532 R569 R673 R683 = 1R_10KOhmResistor1_16W0402: Cost10K: 0; Mistral Part No: 110011060003-R
R272 R275 R562 R721 = 1R_4.7KOhmResistor1_16W0402: Cost100: 0; Cost10K: 0.02; Mistral Part No: 110014060028-R
R274 = 1R_49.9OhmResistor1_16W0402: Cost100: 0.06; Cost10K: 0.06; Mistral Part No: 110014060026-R
R276 R341 R342 R574 R575 R679 = 1R_2.2KOhmResistor1_16W0402: Cost100: 0.05; Cost10K: 0; Mistral Part No: 110014060053-R
R277 = 1R_9.1KohmResistor1_16W1%0402: Cost100: 0.01; Cost10K: 0; DescriptiveText: RES SMD 9.1K OHM 1% 1/16W 0402; MfrNum: MCR01MRTF9101; Mistral Part No: M110016080005
U13 = 1A_TPS79333: MfrNum: TPS79333DBVR; Mistral Part No: 142015020002-R
U14 = 1A_TPD2E001DRL: MfrNum: TPD2E001DRLR; Mistral Part No: M130016080007
U15 = 1A_FT2232_2: Cost10K: 3.1; Mistral Part No: 143014050006-R
U16 = 1A_SN74LVC1G00DCK: MfrNum: SN74LVC1G00DCKR; Mistral Part No: 141010060014-R
U17 = 1A_SN74LVC2G07: MfrNum: SN74LVC2G07DCKR; PACKAGE: 1
U18 = 1A_93C56EEPROM2Kbit: Mistral Part No: 141114050005-R
U62 U68 U69 = 1A_SN74AVC4T245: MfrNum: SN74AVC4T245PWR; Mistral Part No: 141009030111-R
U64 U65 = 1A_SN74AVC2T244: MfrNum: SN74AVC2T244DQMR; Mistral Part No: 141016030002-R
Y4 = 1Y_Crystal12MHzABM3: Cost10K: 0.5; Mistral Part No: 130016020045-R
C181 = 47nFCapacitor16V10%0402: Cost10K: 0.04; Loading: DNI; Mistral Part No: 120009050001-R
C309 C324 C329 C331 C357 = 1C_1uFCapacitor10V10%0402: Cost100: 0.33; Cost10K: 0.2; Mistral Part No: 120014050010-R
C330 C339-C342 = 1C_0.22uFCapacitor50V10%0603: Cost100: 0.01; Cost10K: 0; Mistral Part No: 120011060009-R
C332 C337 C376 = 1C_22uFCapacitor16V10%0805: Mistral Part No: 120014060009-R
C333 = 1C_6.8pFCapacitor50V10%SMD0402: Cost10K: 0.05; Mistral Part No: 120010080029-R
C335 = 1C_2200pFCapacitor50V10%SMD0402: Cost10K: 0.05; Mistral Part No: 120014050012-R
C298 C310 C338 = 1C_0.001uFCapacitor50V5%0402: Cost100: 0.01; Cost10K: 0; Mistral Part No: 120011060017-R
D14 = Diode200mA30V_Schottky: Mistral Part No: 130011050032-R
D15 = 1E_Diode1A20V_Schottky: Cost10K: 0.27; Mistral Part No: 130009030213-P
J44 = 2C_Conn_FPC_0.5mmpitch_50posbot: DescriptiveText: 50 Position FFC, FPC Connector Contacts, Bottom 0.020" (0.50mm) Surface Mount, Right Angle; MfrNum: FH12S-50S-0.5SH(55); Mistral Part No: 150016020021-R
J45 = 2C_Conn_FPC_527450897: Mistral Part No: 150014050029-R
L8 = 1L_4.7uHInductor30%1.7Asmd: Cost10K: 0.58; Mistral Part No: 130011050012-R
L23 = 1L_4.7uHInductor20%450mAsmd: Cost10K: 0.16; Mistral Part No: 130009060029-P
Q3 = 1Q_MOSFET_NChan_BSS138: Cost10K: 0.03; Mistral Part No: M130016080005
Q12 = 1Q_NPN_FMMT458: Mistral Part No: 130011040018-R
R283 R294 = 1R_499Kohm1_16W1%smd0402: Cost100: 0; Cost10K: 0.02; Mistral Part No: 110009090015-P
R284 = 1R_442Kohm1_16W1%smd0402: Cost100: 0; Cost10K: 0; Mistral Part No: 110014060041-R
R285 = 1R_357Kohm1_10W1%smd0402: Cost100: 0; Cost10K: 0; Mistral Part No: 110014060049-R
R286 = 1R_15Kohm1_16W1%smd0402: Cost100: 0; Cost10K: 0.02; Mistral Part No: 110014060042-R
R287 = 1R_680Kohm1_16W1%smd0402: Cost100: 0; Cost10K: 0.02; Mistral Part No: 110014060042-R
R288 = 1R_100KOhmResistor1_16W0402: Cost100: 0.01; Cost10K: 0; Mistral Part No: 110014060043-R
R290 = 1R_49.9KOhmResistor1_16W0402: Cost100: 0; Cost10K: 0.02; Mistral Part No: 110014060031-R
R291 = 1R_60.4Kohm1_16W1%smd0402: Cost100: 0; Cost10K: 0.02; Mistral Part No: 110014060047-R
R301 = 1R_10ohm1_16W5%smd0402: Cost10K: 0; Mistral Part No: 110014060037-R
R303 = 1R_71.5Kohm1_10W1%smd0402: Mistral Part No: 110009080026-R
R304 = 1R_2OhmResistor1_10W1%0603: Cost100: 0; Cost10K: 0.02; Mistral Part No: 110009110001-P
TP33-TP35 TP38 TP54 = 2H_TestPointThroughHole: Cost100: 0.16; Cost10K: 0.1; Mistral Part No: 160016120008-R
TP16 TP36 TP37 TP48-TP51 = 2H_Testpoint_SMD1mmCircle
U19 = 1A_TPS61081DRC: Cost10K: 0.5; MfrNum: TPS61081DRCR; Mistral Part No: 142009100003
U43 = 1A_TPS65105PWP: MfrNum: TPS65105PWPR; Mistral Part No: 142011050004-R
U44 = 1A_SN74LVC1G07: MfrNum: SN74LVC1G07DCKR; Mistral Part No: 141014060023-R
U45 U48 = 1A_SN74LVC32244: MfrNum: SN74LVC32244ZKER; Mistral Part No: 141014060009-R
U66 U67 = 1A_SN74LVC1G04: Cost10K: 0.23; MfrNum: SN74LVC1G04DCKR; Mistral Part No: 141009070007-R
J15 J35 = 2H_Header12x2: Cost10K: 0.57; Mistral Part No: 150014050022-R
C358 C359 C373 C374 = 1C_0.1uFCapacitor50V10%0402: Cost10K: 0.02; MfrNum: C1005X7R1H104K050BB; Mistral Part No: 120011100014-R
C188 C191 C196 C198 C200 C203 C299 C311 C361-C366 = 1C_0.1uFCapacitor16V10%0402: Cost10K: 0.01; MfrNum: C0402C104K4RACTU; Mistral Part No: 120009030060-R
D21 = Diode200mA250V: Mistral Part No: 130014060029-R
FB9-FB11 = 1L_FerriteBead_300ohm500mA: Cost100: 0.06; Cost10K: 0.04; MfrNum: MMZ1608R301ATA00; Mistral Part No: 130014060028-R
J32 = 2C_Conn_HDMI_TypeA: Mistral Part No: 150010050001
R576 = 1R_51Kohm1_16W1%smd0402: Cost100: 0.01; Cost10K: 0; Mistral Part No: 110014060030-R
R577 = 1R_4.3KOhmResistor1_16W0402: Cost100: 0; Cost10K: 0.02; Mistral Part No: 110014060029-R
R579 = 1R_10KOhmResistor1_10W1%0402: Cost100: 0.01; Cost10K: 0; Mistral Part No: 110015050015-R
R580 R582 = 1R_4.7KOhmResistor1_16W0402: Cost100: 0; Cost10K: 0.02; Loading: DNI; Mistral Part No: 110014060028-R
R581 = 1R_10KOhmResistor1_16W0402: Cost10K: 0; Loading: DNI; Mistral Part No: 110011060003-R
U42 = 1A_TPS71712: Cost10K: 4.7; MfrNum: TPS71712DCKR; Mistral Part No: 142014060014-R
U46 = 1A_SIL9022A: Cost100: 10; Cost10K: 1; Mistral Part No: M141016080004
U47 = 1A_TPD12S016: MfrNum: TPD12S016PWR; Mistral Part No: 141011080021
C183-C185 C187 = 1C_0.022uFCapacitor16Vsmd0402: Cost10K: 0.04; DescriptiveText: 0.022µF ±10% 50V Ceramic Capacitor X7R 0402; MfrNum: C1005X7R1H223K050BB; Mistral Part No: M120016080005; PartName: 0.022µF ±10% 50V Ceramic Capacitor X7R 0402
C190 C195 = 1C_1uFCapacitor50V10%0603: Cost10K: 0.04; Mistral Part No: M120016080002
C192 C193 = 1C_47uFCapacitor16V20%1206: MfrNum: C3216X5R1C476M160AB; Mistral Part No: 120011060001-R
C201 C204 C205 = 1C_0.47uFCapacitor16V10%0402: Cost10K: 0.02; Mistral Part No: 120009030119
C438 = 1C_0.01uFCapacitor16V10%0402: Cost100: 0; Cost10K: 0.01; Loading: DNI; Mistral Part No: 120009030032-R
J17 J18 = 2C_Conn_3.5mm_SJ3524SMT: Mistral Part No: M150016080004
R328 R329 R337 R338 = 1R_402ohm1_10W1%smd0603: Cost100: 0; Cost10K: 0.02; Mistral Part No: M110016080006
R331 = 1R_22OhmResistor1_16W1%0402: Cost100: 0.06; Cost10K: 0; DescriptiveText: RES SMD 22 OHM 1% 1/16W 0402; MfrNum: MCR01MRTF22R0; Mistral Part No: 110014060035-R
SPKR1 SPKR2 = 1G_Speaker_AS01808: Mistral Part No: M160016080002
U20 = 1A_TLV320AIC3111: MfrNum: TLV320AIC3111IRHBR; Mistral Part No: 143014080001-R
U70 = 1A_SN74LVC1G125: Cost10K: 0.09; Loading: DNI; Mistral Part No: 141009030231
U85 U88 = SN74LVC1G08DCKT_SC70: MfrNum: SN74LVC1G08DCKR; Mistral Part No: 141009030227
Y5 = 1Y_Oscillator_12MHz: Cost10K: 2.45; Mistral Part No: 130014060041-R
J36 = 2C_Conn_Molex_53398_Male: Mistral Part No: M150016080008
L24 = 1L_AP-HA3040: Cost10K: 0.58; Mistral Part No: M130016080002
U1 = am438x_ZDN_ePOS_EVM_13: MfrNum: XAM4384CZDNA100S; Mistral Part No: 141214060001
J37 = Header6x2FTR: Mistral Part No: M150016080009

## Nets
AGND_AUD: C183.2 C184.2 C185.2 C186.2 C187.2 C188.2 C189.2 C190.2 C191.2 C194.2 C195.2 C196.2 C197.2 C198.2 C201.2 FB6.1 J17.1(P1) J18.1(P1) U20.16(AVSS) U20.20(SPLVSS) U20.25(SPRVSS) U20.29(HPVSS)
AVDD10_FB: C333.2 R284.1(P1) R291.1 U43.1(FB1)
AVDD10_IND: D15.2(ANODE) L23.2 U43.5(SW1) U43.6(SW2)
DGND: C144.2 C145.2 C146.2 C147.2 C148.2 C149.2 C150.2 C151.2 C152.2 C153.2 C154.2 C155.2 C156.2 C157.2 C158.2 C159.2 C160.2 C161.2 C162.2 C163.2 C164.2 C165.2 C166.2 C177.2 C178.2 C179.2 C180.2 C181.2 C182.2 C199.2 C200.2 C202.2 C203.2 C220.2 C221.2 C222.2 C223.2 C260.2 C309.2 C324.2 C325.2 C329.2 C330.2 C331.2 C332.2 C334.2 C336.2 C337.2 C338.2 C339.2 C341.2 C357.2 C358.2 C359.2 C360.2 C361.2 C362.2 C363.2 C364.2 C365.2 C366.2 C367.2 C368.2 C369.2 C370.2 C371.2 C372.2 C373.2 C374.2 C375.2 C376.2 C377.2 C378.2 C379.2 C382.2 C383.2 C384.2 C405.2 C427.2 C434.2 C435.2 C436.2 C437.2 C438.2 C479.2 C485.2 D14.2(CATHODE) FB6.2 FB18.2 J12.5(GND) J15.11 J15.12 J15.21 J32.2(DAT2_S) J32.5(DAT1_S) J32.8(DAT0_S) J32.11(CLK_S) J32.17(DDC/CEC_GND) J32.MTG1 J32.MTG2 J32.MTG3 J32.MTG4 J35.2 J35.4 J35.6 J35.9 J35.12 J35.15 J44.5 J44.8 J44.36 J44.38 J44.48 J44.MNT1 J44.MNT2 J45.7 J45.MNT1 J45.MNT2 Q3.S(SOURCE) R267.2(P2) R271.1(P1) R275.1(P1) R277.1(P1) R280.2(P2) R285.2 R286.2(P2) R290.1(P1) R291.2 R303.1(P1) R304.1 R305.1(P1) R330.1(P1) R568.1(P1) R573.1(P1) R577.1(P1) R579.1 R581.1(P1) R673.1(P1) R679.1(P1) R721.1(P1) U13.2(GND) U14.4(GND) U15.1(GND.1) U15.5(GND.2) U15.10(AGND) U15.11(GND.3) U15.13(TEST) U15.15(GND.4) U15.25(GND.5) U15.35(GND.6) U15.47(GND.7) U15.51(GND.8) U16.3(GND) U17.2(GND) U17.3(2A) U18.5(VSS) U18.7(NC1) U19.4(GND) U19.8(PGND) U19.PAD(TPAD) U20.1(IOVSS) U20.18(DVSS) U20.TPAD U42.2(GND) U43.7(PGND) U43.8(PGND) U43.15(C2-/MODE) U43.19(GND) U43.TP(THERM_GND) U44.3(GND) U45.B3(GND1) U45.B4(GND16) U45.D3(GND2) U45.D4(GND15) U45.E3(GND3) U45.E4(GND14) U45.G3(GND4) U45.G4(GND13) U45.K3(GND5) U45.K4(GND12) U45.M3(GND6) U45.M4(GND11) U45.N3(GND7) U45.N4(GND10) U45.R3(GND8) U45.R4(GND9) U46.43(CGND) U46.55(RSVDL) U46.57(IOGND) U46.63(AGND) U46.70(VDDQ) U46.EPAD U47.6(GND) U47.14(GND) U47.19(GND) U48.B3(GND1) U48.B4(GND16) U48.D3(GND2) U48.D4(GND15) U48.E3(GND3) U48.E4(GND14) U48.G3(GND4) U48.G4(GND13) U48.K3(GND5) U48.K4(GND12) U48.M3(GND6) U48.M4(GND11) U48.N3(GND7) U48.N4(GND10) U48.R3(GND8) U48.R4(GND9) U62.8(GND) U62.9(GND) U64.5(GND) U65.5(GND) U66.3(GND) U67.3(GND) U68.2(1DIR) U68.8(GND) U68.9(GND) U69.8(GND) U69.9(GND) U70.3(GND) U85.3(GND) U88.3(GND) Y5.2(GND) ; also on sheet 9 10 11 13 14 15 16 17 18 19 20 21 22 23 24 25 26 27 28 30 31
GNDA_ADC: C310.2 C311.2 C380.2 C381.2 J35.21 J37.5 J37.11 J37.12 R631.2(P2) U1.AE14(ADC0_VREFN) ; also on sheet 21
GNDA_MAG: C298.2 C299.2 J36.7 J36.MNT1 J36.MNT2 L24.G1(GND) L24.G2(GND) R631.1(P1) U1.AD15(ADC1_VREFN)
GNDUSBJ: FB18.1 J12.S1 J12.S2 J12.S3 J12.S4
V1_2D: C309.1 C368.1 C376.1 FB9.2 FB11.2 U42.5(OUT)
V1_2D_EN: R297.1(P1) U42.3(EN)
V1_8AUD: C202.1 C203.1 FB5.2 U20.3(DVDD)
V1_8D: C380.1 FB5.1 J37.6 ; also on sheet 18 19 30
V1_8FTDI: C149.1 C150.1 C152.1 C158.1 U15.12(VCORE.1) U15.37(VCORE.2) U15.49(VREGOUT) U15.64(VCORE.3)
V3_3AUD: C186.1 C188.1 C197.1 C198.1 FB4.2 U20.17(AVDD) U20.28(HPVDD)
V3_3D: C177.1 C199.1 C200.1 C220.1 C222.1 C260.1 C325.1 C334.1 C367.1 C369.1 C370.1 C371.1 C372.1 C377.1 C382.1 C383.1 C384.1 C405.1 C427.1 C434.1 C435.1 C436.1 C437.1 C438.1 C479.1 C485.1 D21.2(Anode) FB4.1 FB10.2 J35.5 J45.8 R292.2(P2) R297.2(P2) R299.2(P2) R300.2(P2) R305.2(P2) R530.2(P2) R532.2(P2) R562.2(P2) R569.2(P2) R574.2(P2) R575.2(P2) R584.2(P2) R683.2(P2) U20.2(IOVDD) U44.5(VCC) U45.C3(VCC) U45.C4(VCC) U45.F3(VCC) U45.F4(VCC) U45.L3(VCC) U45.L4(VCC) U45.P3(VCC) U45.P4(VCC) U47.24(VCCA) U48.C3(VCC) U48.C4(VCC) U48.F3(VCC) U48.F4(VCC) U48.L3(VCC) U48.L4(VCC) U48.P3(VCC) U48.P4(VCC) U62.16(VCCB) U64.1(VCCA) U64.3(A2) U65.8(VCCB) U66.5(VCC) U67.5(VCC) U68.1(VCCA) U68.3(2DIR) U68.16(VCCB) U69.1(VCCA) U69.2(1DIR) U69.3(2DIR) U69.16(VCCB) U70.5(VCC) U85.5(VCC) U88.5(VCC) Y5.4(VCC) ; also on sheet 9 10 11 13 15 17 18 19 20 21 22 23 24 25 26 27 28 30 31
V3_3FTDI: C147.1 C151.1 C157.1 C159.1 C160.1 C161.1 C162.1 C165.1 C166.1 C178.1 C221.1 C223.1 D4.2(Anode) FB2.2 FB3.2 R270.2(P2) R278.2(P2) U13.5(OUT) U15.20(VCCIO.1) U15.31(VCCIO.2) U15.42(VCCIO.3) U15.50(VREGIN) U15.56(VCCIO.4) U16.5(VCC) U17.5(VCC) U18.6(NC2) U18.8(VCC) U62.1(VCCA) U62.2(1DIR) U62.3(2DIR) U64.8(VCCB) U65.1(VCCA) ; also on sheet 20
V5_0D: C378.1 R580.2(P2) R582.2(P2) U47.11(VCC5V) ; also on sheet 10 30
V5_0HDMICONN: C379.1 J32.18(+5V) U47.13(5V_OUT)
VBAT: C179.1 C189.1 C190.1 C191.1 C194.1 C195.1 C196.1 C329.1 C337.1 C357.1 J35.1 J35.3 L23.1 Q12.1(C) R289.1(P1) R293.2(P2) R302.2(P2) R307.1(P1) U19.2(VIN) U20.21(SPLVDD) U20.24(SPRVDD) U42.1(IN) U43.4(VIN) ; also on sheet 14 15 16 19 24 28 30
VDDA_ADC: C310.1 C311.1 C381.1 J35.23 U1.AD14(ADC0_VREFP) ; also on sheet 21
VDDA_MAGADC: C298.1 C299.1 U1.AE15(ADC1_VREFP) ; also on sheet 21
VDDLCD_BASE: Q12.3(B) U43.3(BASE)
AIC_RESETn: R466.2(P2) U85.4(Y)
AM438X_AIN0: R498.2(P2) U1.AA12(ADC0_AIN0)
AM438X_AIN1: R499.2(P2) U1.Y12(ADC0_AIN1)
AM438X_AIN2: R502.2(P2) U1.Y13(ADC0_AIN2)
AM438X_AIN3: J35.24 R504.2(P2) TP38.1 U1.AA13(ADC0_AIN3)
AM438X_AIN4: J35.22 R500.1(P1) TP34.1 U1.AB13(ADC0_AIN4)
AM438X_AIN5: J35.20 R501.1(P1) TP33.1 U1.AC13(ADC0_AIN5)
AM438X_AIN6: R503.1(P1) U1.AD13(ADC0_AIN6)
AM438X_AIN7: R505.1(P1) U1.AE13(ADC0_AIN7) ; also on sheet 30
AM438X_AUD_BITCLK: R387.2(P2) U1.L23(MCASP0_ACLKR/MCASP1_ACLKX)
AM438X_AUD_FSYNC: R389.2(P2) U1.K23(MCASP0_FSR/MCASP1_FSX)
AM438X_CAM1_DATA0: R309.2(P2) U1.AB20(CAM1_DATA0/UART1_RXD) ; also on sheet 17
AM438X_CAM1_DATA1: R311.2(P2) U1.AC21(CAM1_DATA1/UART1_TXD) ; also on sheet 17
AM438X_CAM1_DATA2: R312.2(P2) U1.AD21(CAM1_DATA2/UART1_CTSn) ; also on sheet 17
AM438X_CAM1_DATA3: R317.2(P2) U1.AE22(CAM1_DATA3/UART1_RTSn) ; also on sheet 17
AM438X_CAM1_DATA4: R319.2(P2) U1.AD22(CAM1_DATA4/UART1_RIN) ; also on sheet 17
AM438X_CAM1_DATA5: R321.2(P2) U1.AE23(CAM1_DATA5/UART1_DSRn) ; also on sheet 17
AM438X_CAM1_DATA6: R313.1(P1) U1.AD23(CAM1_DATA6/UART1_DCDn) ; also on sheet 17
AM438X_CAM1_DATA7: R314.1(P1) U1.AE24(CAM1_DATA7/UART1_DTRn) ; also on sheet 17
AM438X_CAM1_DATA8: R316.1(P1) U1.AD24(CAM1_DATA8)
AM438X_CAM1_DATA9: R318.1(P1) U1.AC24(CAM1_DATA9)
AM438X_CAM1_HSYNC: R310.1(P1) U1.AD25(CAM1_HD)
AM438X_CAM1_PCLK: R315.2(P2) U1.AE21(CAM1_PCLK)
AM438X_CAM1_VSYNC: R308.1(P1) U1.AC23(CAM1_VD)
AM438X_I2C_SCL2: R571.2(P2) ; also on sheet 13
AM438X_I2C_SDA2: R572.2(P2) ; also on sheet 13
AM438X_LCD_AC_BIAS_EN: TP51.1 U1.A24(DSS_AC_BIAS_EN) U45.B6(1A4) U48.T6(8A4) ; also on sheet 11 24
AM438X_LCD_DATA0: U1.B22(DSS_DATA0) U45.E5(3A1) U48.A6(1A2) ; also on sheet 11 24
AM438X_LCD_DATA1: U1.A21(DSS_DATA1) U45.E6(3A2) U48.B5(1A3) ; also on sheet 11 24
AM438X_LCD_DATA2: U1.B21(DSS_DATA2) U45.F5(3A3) U48.B6(1A4) ; also on sheet 11 24
AM438X_LCD_DATA3: U1.C21(DSS_DATA3) U45.F6(3A4) U48.E5(3A1) ; also on sheet 11 24
AM438X_LCD_DATA4: U1.A20(DSS_DATA4) U45.G5(4A1) U48.E6(3A2) ; also on sheet 11 24
AM438X_LCD_DATA5: U1.B20(DSS_DATA5) U45.G6(4A2) U48.F5(3A3) ; also on sheet 11
AM438X_LCD_DATA6: U1.C20(DSS_DATA6) U45.H5(4A3) U48.F6(3A4) ; also on sheet 11 24
AM438X_LCD_DATA7: U1.E19(DSS_DATA7) U45.H6(4A4) U48.G5(4A1) ; also on sheet 11 24
AM438X_LCD_DATA8: U1.A19(DSS_DATA8) U45.J5(5A1) U48.G6(4A2) ; also on sheet 11
AM438X_LCD_DATA9: U1.B19(DSS_DATA9) U45.J6(5A2) U48.H5(4A3) ; also on sheet 11
AM438X_LCD_DATA10: U1.A18(DSS_DATA10) U45.K5(5A3) U48.H6(4A4) ; also on sheet 11
AM438X_LCD_DATA11: U1.B18(DSS_DATA11) U45.K6(5A4) U48.J5(5A1) ; also on sheet 11
AM438X_LCD_DATA12: U1.C19(DSS_DATA12) U45.L5(6A1) U48.J6(5A2) ; also on sheet 11
AM438X_LCD_DATA13: U1.D19(DSS_DATA13) U45.L6(6A2) U48.K5(5A3) ; also on sheet 11
AM438X_LCD_DATA14: U1.C17(DSS_DATA14) U45.M5(6A3) U48.K6(5A4) ; also on sheet 11
AM438X_LCD_DATA15: U1.D17(DSS_DATA15) U45.M6(6A4) U48.L5(6A1) ; also on sheet 11
AM438X_LCD_DATA16: U1.A11(GPMC_AD15/DSS_DATA16) U45.N5(7A1) U48.L6(6A2)
AM438X_LCD_DATA17: U1.B11(GPMC_AD14/DSS_DATA17) U45.N6(7A2) U48.M5(6A3)
AM438X_LCD_DATA18: U1.C11(GPMC_AD13/DSS_DATA18) U45.P5(7A3) U48.M6(6A4)
AM438X_LCD_DATA19: U1.E11(GPMC_AD12/DSS_DATA19) U45.P6(7A4) U48.N5(7A1)
AM438X_LCD_DATA20: U1.D11(GPMC_AD11/DSS_DATA20) U45.R5(8A1) U48.N6(7A2)
AM438X_LCD_DATA21: U1.F11(GPMC_AD10/DSS_DATA21) U45.R6(8A2) U48.P5(7A3)
AM438X_LCD_DATA22: U1.A10(GPMC_AD9/DSS_DATA22) U45.T5(8A3) U48.P6(7A4)
AM438X_LCD_DATA23: U1.B10(GPMC_AD8/DSS_DATA23) U45.T6(8A4) U48.R5(8A1)
AM438X_LCD_HSYNC: TP49.1 U1.A23(DSS_HSYNC) U45.B5(1A3) U48.R6(8A2) ; also on sheet 11 24
AM438X_LCD_PCLK: TP48.1 U1.A22(DSS_PCLK) U45.A5(1A1) U48.A5(1A1)
AM438X_LCD_VSYNC: TP50.1 U1.B23(DSS_VSYNC) U45.A6(1A2) U48.T5(8A3) ; also on sheet 11
AM438X_MAGAIN0: J36.1 U1.AC16(ADC1_AIN0)
AM438X_MAGAIN1: J36.2 U1.AB16(ADC1_AIN1)
AM438X_MAGAIN2: J36.3 U1.AA16(ADC1_AIN2)
AM438X_MAGAIN3: J36.4 U1.AB15(ADC1_AIN3)
AM438X_MAGAIN4: J36.5 U1.AA15(ADC1_AIN4)
AM438X_MAGAIN5: J36.6 U1.Y15(ADC1_AIN5)
AM438X_MAGAIN6: TP36.1 U1.AE16(ADC1_AIN6)
AM438X_MAGAIN7: TP37.1 U1.AD16(ADC1_AIN7)
AM438X_MCASP1_AXR0: R397.2(P2) U1.M25(MCASP0_AXR1/MCASP1_AXR0)
AM438X_MCASP1_AXR1: R559.2(P2) U1.L24(MCASP0_AHCLKX/MCASP1_AXR1)
AM438X_PORZn: R687.1(P1) ; also on sheet 31
AUD_BITCLK: U20.7(BCLK) U68.13(1B1)
AUD_DIN: U20.5(DIN) U68.11(2B1)
AUD_DOUT: R559.1(P1) U20.4(DOUT) U70.2(A) U70.4(Y)
AUD_FSYNC: U20.6(WCLK) U68.12(1B2)
AUD_HPLOUT: C192.1 U20.27(HPL)
AUD_HPLOUT_CONN: C192.2 J17.2(P2)
AUD_HPROUT: C193.1 U20.30(HPR)
AUD_HPROUT_CONN: C193.2 J17.3(P3)
AUD_MCLK: U20.8(MCLK) U68.10(2B2)
AUD_MICBIAS: R341.1(P1) R342.1(P1) U20.12(MICBIAS)
AUD_MICDET: R340.2(P2) U20.11(VOL/MICDET)
AUD_MICL: C205.2 R340.1(P1) U20.13(MIC1LP)
AUD_MICL_CONN: C205.1 J18.2(P2) R342.2(P2)
AUD_MICR: C204.2 U20.14(MIC1RP)
AUD_MICR_CONN: C204.1 J18.3(P3) R341.2(P2)
AUD_RESETn: R466.1(P1) U20.31(~{RESET})
AUD_SPKRETL: R338.2(P2) SPKR2.2(-) U20.19(SPLM)
AUD_SPKRETR: R329.2(P2) SPKR1.2(-) U20.23(SPRM)
AUD_SPKROUTL: R337.2(P2) SPKR2.1(+) U20.22(SPLP)
AUD_SPKROUTR: R328.2(P2) SPKR1.1(+) U20.26(SPRP)
AUDIO_MSTRCLK: R326.2(P2) R331.1(P1) U68.7(2A2) U69.7(2A2)
BKLT_EN: Q3.G(GATE) R300.1(P1) R306.1(P1)
BKLT_L: L8.1 U19.1(L)
BKLT_SW: L8.2 U19.10(SW)
CAM1_DATA0: J15.3 R309.1(P1)
CAM1_DATA1: J15.5 R311.1(P1)
CAM1_DATA2: J15.7 R312.1(P1)
CAM1_DATA3: J15.13 R317.1(P1)
CAM1_DATA4: J15.15 R319.1(P1)
CAM1_DATA5: J15.17 R321.1(P1)
CAM1_DATA6: J15.6 R313.2(P2)
CAM1_DATA7: J15.8 R314.2(P2)
CAM1_DATA8: J15.10 R316.2(P2)
CAM1_DATA9: J15.14 R318.2(P2)
CAM1_FIELD: J15.20 R324.2(P2)
CAM1_GIO0: J15.16 R320.2(P2)
CAM1_HSYNC: J15.4 R310.2(P2)
CAM1_I2C_DTA: J15.24 R327.2(P2)
CAM1_I2C_SCL: J15.22 R325.2(P2)
CAM1_PCLK: J15.9 R315.1(P1)
CAM1_SRCCLK: J15.23 R326.1(P1)
CAM1_VSYNC: J15.2 R308.2(P2)
CAM1_WEN: J15.19 R323.1(P1)
CAM_BUF_EN: J15.18 R322.2(P2)
COMP: C335.2 U43.22(COMP)
COMP_CAP: C335.1 R286.1(P1)
EMU_USB_DM: J12.2(DM) U14.5(IO2) U15.7(DM)
EMU_USB_DP: J12.3(DP) U14.3(IO1) U15.8(DP)
F_ADBUS0: R260.2(P2) U15.16(ADBUS0)
F_ADBUS1: R261.2(P2) U15.17(ADBUS1)
F_ADBUS2: R262.2(P2) U15.18(ADBUS2)
F_ADBUS3: R263.2(P2) U15.19(ADBUS3)
F_ADBUS4: R264.2(P2) U15.21(ADBUS4)
F_ADBUS5: R266.2(P2) U15.26(ACBUS0)
F_ADBUS6: R265.2(P2) U15.23(ADBUS6)
F_ADBUS7: R269.2(P2) U15.30(ACBUS4)
FT_SRESET: R266.1(P1) R275.2(P2) U16.1(A)
FT_VBUS: R273.1(P1) R721.2(P2) U16.2(B)
FTDI_BDBUS0_TXD: U15.38(BDBUS0) ; also on sheet 20
FTDI_BDBUS1_RXD: U15.39(BDBUS1) ; also on sheet 20
FTDI_BDBUS2_RTSn: U15.40(BDBUS2) ; also on sheet 20
FTDI_BDBUS3_CTSn: U15.41(BDBUS3) ; also on sheet 20
FTDI_XIN: C163.1 U15.2(XTIN) Y4.2
FTDI_XOUT: C164.1 U15.3(XTOUT) Y4.1
GP_I2C_SCL: R325.1(P1) R513.1(P1) U20.10(SCL) ; also on sheet 11 30
GP_I2C_SDA: R327.1(P1) R514.1(P1) U20.9(SDA) ; also on sheet 11 30
GPIO5_4: J35.7 U1.P25(GPIO5_4)
GPIO5_5: J35.18 U1.R24(GPIO5_5)
GPIO5_6: J35.11 U1.P24(GPIO5_6)
GPIO5_7: J35.13 U1.N25(GPIO5_7)
GPIO5_8: J35.17 R249.2(P2) U1.D25(GPIO5_8)
GPIO5_9: J35.8 U1.F24(GPIO5_9)
GPIO5_10: J35.10 U1.G20(GPIO5_10)
GPIO5_11: J35.14 U1.F23(GPIO5_11)
GPIO5_12: J35.16 U1.E25(GPIO5_12)
GPIO5_13: J35.19 R250.2(P2) U1.E24(GPIO5_13)
GPMC_A0/GPIO: U88.2(B) ; also on sheet 28
GPMC_BE1n_GPIO: U85.2(B) ; also on sheet 9
HDMI_CEC: R576.1(P1) U46.71(CEC_A) U47.1(CEC_A)
HDMI_CEC_D: R578.2(P2) U46.50(CEC_D)
HDMI_CLK+: J32.10(CLK+) U46.59(TXC+) U47.16(TMDS_CK+)
HDMI_CLK-: J32.12(CLK-) U46.58(TXC-) U47.15(TMDS_CK-)
HDMI_CT_HPD: R583.2(P2) R584.1(P1) U47.12(CT_HPD)
HDMI_D0: U45.E2(3Y1) U46.32(VDATA_IN0)
HDMI_D1: U45.E1(3Y2) U46.31(VDATA_IN1)
HDMI_D2: U45.F2(3Y3) U46.30(VDATA_IN2)
HDMI_D3: U45.F1(3Y4) U46.29(VDATA_IN3)
HDMI_D4: U45.G2(4Y1) U46.28(VDATA_IN4)
HDMI_D5: U45.G1(4Y2) U46.27(VDATA_IN5)
HDMI_D6: U45.H2(4Y3) U46.25(VDATA_IN6)
HDMI_D7: U45.H1(4Y4) U46.24(VDATA_IN7)
HDMI_D8: U45.J2(5Y1) U46.23(VDATA_IN8)
HDMI_D9: U45.J1(5Y2) U46.20(VDATA_IN9)
HDMI_D10: U45.K2(5Y3) U46.19(VDATA_IN10)
HDMI_D11: U45.K1(5Y4) U46.18(VDATA_IN11)
HDMI_D12: U45.L2(6Y1) U46.17(VDATA_IN12)
HDMI_D13: U45.L1(6Y2) U46.16(VDATA_IN13)
HDMI_D14: U45.M2(6Y3) U46.15(VDATA_IN14)
HDMI_D15: U45.M1(6Y4) U46.14(VDATA_IN15)
HDMI_D16: U45.N2(7Y1) U46.13(VDATA_IN16)
HDMI_D17: U45.N1(7Y2) U46.11(VDATA_IN17)
HDMI_D18: U45.P2(7Y3) U46.10(VDATA_IN18)
HDMI_D19: U45.P1(7Y4) U46.9(VDATA_IN19)
HDMI_D20: U45.R2(8Y1) U46.8(VDATA_IN20)
HDMI_D21: U45.R1(8Y2) U46.7(VDATA_IN21)
HDMI_D22: U45.T2(8Y3) U46.6(VDATA_IN22)
HDMI_D23: U45.T1(8Y4) U46.4(VDATA_IN23)
HDMI_DE: U45.B1(1Y4) U46.33(DE)
HDMI_EXTSWING: R577.2(P2) U46.56(EXT_SWING)
HDMI_HPLG: R579.2 U46.54(HPD) U47.4(HPD_A)
HDMI_HSYNC: U45.B2(1Y3) U46.34(HSYNC)
HDMI_I2C_SCL: R571.1(P1) U46.1(CSCL)
HDMI_I2C_SDA: R572.1(P1) U46.2(CSDA)
HDMI_I2CSCL: R574.1(P1) U46.49(DSCL) U47.2(SCL_A)
HDMI_I2CSDA: R575.1(P1) U46.48(DSDA) U47.3(SDA_A)
HDMI_INTn: R569.1(P1) U46.52(INT) ; also on sheet 28
HDMI_LSOE: R583.1(P1) U47.5(LS_OE)
HDMI_PCLK: U45.A2(1Y1) U46.22(IDCK)
HDMI_RESETn: R565.2(P2) U88.4(Y)
HDMI_RESETn_R: R565.1(P1) U46.51(RESETn)
HDMI_TX0+: J32.7(DAT0+) U46.62(TX0+) U47.18(TMDS_D0+)
HDMI_TX0-: J32.9(DAT0-) U46.61(TX0-) U47.17(TMDS_D0-)
HDMI_TX1+: J32.4(DAT1+) U46.65(TX1+) U47.21(TMDS_D1+)
HDMI_TX1-: J32.6(DAT1-) U46.64(TX1-) U47.20(TMDS_D1-)
HDMI_TX2+: J32.1(DAT2+) U46.68(TX2+) U47.23(TMDS_D2+)
HDMI_TX2-: J32.3(DAT2-) U46.67(TX2-) U47.22(TMDS_D2-)
HDMI_VSYNC: U45.A1(1Y2) U46.35(VSYNC)
HDMICONN_CEC: J32.13(CEC) U47.7(CEC_B)
HDMICONN_HPLG: J32.19(HPLG) R581.2(P2) U47.10(HPD_B)
HDMICONN_I2CSCL: J32.15(SCL) R580.1(P1) U47.8(SCL_B)
HDMICONN_I2CSDA: J32.16(SDA) R582.1(P1) U47.9(SDA_B)
JTAG_EMU0: U65.7(B1) ; also on sheet 28
JTAG_EMU1: U65.6(B2) ; also on sheet 28
JTAG_TCK: U62.13(1B1) ; also on sheet 11
JTAG_TDI: U62.12(1B2) ; also on sheet 11
JTAG_TDO: U64.2(A1) ; also on sheet 11
JTAG_TMS: U62.11(2B1) ; also on sheet 11
JTAG_TRSTn: U62.10(2B2) ; also on sheet 11
JTAGPOD_PRES: R669.1(P1) ; also on sheet 11
LCD_AVDD_EN: R293.1(P1) TP35.1 U43.24(EN)
LCD_BACKLIGHT: R306.2(P2) U1.G24(ECAP0_IN_PWM0_OUT)
LCD_BLUE0: J44.19 U48.A1(1Y2)
LCD_BLUE1: J44.18 U48.B2(1Y3)
LCD_BLUE2: J44.17 U48.B1(1Y4)
LCD_BLUE3: J44.16 U48.E2(3Y1)
LCD_BLUE4: J44.15 U48.E1(3Y2)
LCD_BLUE5: J44.14 U48.F2(3Y3)
LCD_BLUE6: J44.13 U48.F1(3Y4)
LCD_BLUE7: J44.12 U48.G2(4Y1)
LCD_DITHER: J44.47 R279.1(P1)
LCD_EN: J44.9 U48.T1(8Y4)
LCD_GREEN0: J44.27 U48.G1(4Y2)
LCD_GREEN1: J44.26 U48.H2(4Y3)
LCD_GREEN2: J44.25 U48.H1(4Y4)
LCD_GREEN3: J44.24 U48.J2(5Y1)
LCD_GREEN4: J44.23 U48.J1(5Y2)
LCD_GREEN5: J44.22 U48.K2(5Y3)
LCD_GREEN6: J44.21 U48.K1(5Y4)
LCD_GREEN7: J44.20 U48.L2(6Y1)
LCD_HSYNC: J44.11 U48.R1(8Y2)
LCD_LEFTRIGHT: J44.39 R281.1(P1)
LCD_PCLK: J44.37 U48.A2(1Y1)
LCD_RED0: J44.35 U48.L1(6Y2)
LCD_RED1: J44.34 U48.M2(6Y3)
LCD_RED2: J44.33 U48.M1(6Y4)
LCD_RED3: J44.32 U48.N2(7Y1)
LCD_RED4: J44.31 U48.N1(7Y2)
LCD_RED5: J44.30 U48.P2(7Y3)
LCD_RED6: J44.29 U48.P1(7Y4)
LCD_RED7: J44.28 U48.R2(8Y1)
LCD_RESETn: C324.1 J44.44 R282.1(P1)
LCD_UPDOWN: J44.40 R280.1(P1)
LCD_VSYNC: J44.10 U48.T2(8Y3)
MCASP1_ACLKX: R387.1(P1) U68.4(1A1) U69.4(1A1)
MCASP1_AXR0: R397.1(P1) U68.6(2A1) U69.6(2A1)
MCASP1_FSYNC: R389.1(P1) U68.5(1A2) U69.5(1A2)
MNT1: L24.MNT1
MNT2: L24.MNT2
MON_AIN0: J37.1 R498.1(P1)
MON_AIN1: J37.3 R499.1(P1)
MON_AIN2: J37.7 R502.1(P1)
MON_AIN3: J37.9 R504.1(P1)
MON_AIN4: J37.2 R500.2(P2)
MON_AIN5: J37.4 R501.2(P2)
MON_AIN6: J37.8 R503.2(P2)
MON_AIN7: J37.10 R505.2(P2)
PRINTER_GPIO1: R250.1(P1) ; also on sheet 24
PRINTER_GPIO2: R249.1(P1) ; also on sheet 24
RS232_1_EN: R322.1(P1) ; also on sheet 17 28
SEL_HDMIn: R674.1(P1) U45.A3(1~{OE}) U45.A4(2~{OE}) U45.H3(4~{OE}) U45.H4(3~{OE}) U45.J3(5~{OE}) U45.J4(6~{OE}) U45.T3(8~{OE}) U45.T4(7~{OE})
SEL_LCDn: U48.A3(1~{OE}) U48.A4(2~{OE}) U48.H3(4~{OE}) U48.H4(3~{OE}) U48.J3(5~{OE}) U48.J4(6~{OE}) U48.T3(8~{OE}) U48.T4(7~{OE}) U66.4(Y) U68.14(2~{OE}) U68.15(1~{OE})
SEL_LCDORHDMIn: R292.1(P1) R674.2(P2) U1.A12(GPMC_CLK/GPIO) U44.2(A) U66.2(A) U69.14(2~{OE}) U69.15(1~{OE})
SYS_RESETn: U67.2(A) U85.1(A) U88.1(A) ; also on sheet 9 11 26 31
SYS_WARMRESETn: R718.1(P1) ; also on sheet 24 31
TSC_INTn: R515.1(P1) ; also on sheet 28
USBJTAG_ENn: R669.2(P2) U62.14(2~{OE}) U62.15(1~{OE}) U64.4(~{OE}) U65.4(~{OE})
VCAM_PWR: C182.1 J15.1 R307.2(P2)
VCOMC+: C340.2 U43.16(C1+)
VCOMC-: C340.1 U43.17(C1-)
VCOMIN: C338.1 R283.1(P1) R285.1 U43.11(VCOMIN)
VFTDI_PHY: C153.1 C154.1 FB2.1 U15.4(VPHY)
VFTDI_PLL: C155.1 C156.1 FB3.1 U15.9(VPLL)
VGHFB: R287.1(P1) R290.2(P2) U43.12(FB3)
VGL_DRV: C342.2 U43.18(DRV)
VGL_FB: R288.2(P2) R294.1(P1) U43.21(FB2)
VGL_REF: C330.1 R288.1(P1) U43.20(REF)
VHDMI_AVCC12: C373.1 C374.1 C375.1 FB9.1 U46.60(AVCC12) U46.66(AVCC12)
VHDMI_CVCC12: C361.1 C362.1 C363.1 C364.1 C365.1 C366.1 FB11.1 U46.5(CVCC12) U46.12(CVCC12) U46.26(CVCC12) U46.42(CVCC12) U46.47(CVCC12) U46.53(CVCC12)
VHDMI_IOVCC: C358.1 C359.1 C360.1 FB10.1 U46.3(IOVCC) U46.21(IOVCC) U46.46(IOVCC)
VLCD_AVDD: C332.1 C333.1 D15.1(CATHODE) J44.43 R283.2(P2) R284.2(P2) U43.9(SUPP)
VLCD_DVDD: C336.1 J44.7 Q12.2(E) R279.2(P2) R281.2(P2) R282.2(P2) U43.2(FB4)
VLCD_VCOM: C331.1 J44.6 J44.46 U43.10(VCOM)
VLCD_VGH: C341.1 J44.41 R287.2(P2) U43.13(OUT3)
VLCD_VGL: C339.1 D14.1(ANODE) J44.42 R294.2(P2)
VLED+: C180.1 J44.1 J44.2 U19.9(OUT)
VLED-: J44.3 J44.4 R304.2 U19.5(FB)
VUSB_FTDI: C145.1 C146.1 FB1.2 R272.2(P2) R668.1(P1) U13.1(IN)
VUSB_JTAG: C144.1 FB1.1 J12.1(VBUS) U14.1(VCC)
N12697751: C181.1 R301.2(P2) R303.2(P2) U19.3(SS)
N12697755: R299.1(P1) U19.6(EN)
N12697819: Q3.D(DRAIN) R301.1(P1)
N12697997: R302.1(P1) U19.7(FSW)
N13491412: C201.1 U20.15(MIC1LM)
N13491456: TP16.1 U20.32(GPIO1)
N13954420: R260.1(P1) U62.4(1A1)
N13954468: R261.1(P1) U62.5(1A2)
N13954518: R262.1(P1) U64.7(B1)
N13954568: R263.1(P1) U62.6(2A1)
N13954618: R264.1(P1) U62.7(2A2)
N13954724: R274.2(P2) U15.60(PWREN#)
N13954780: D4.1(Cathode) R274.1(P1)
N13954911: R272.1(P1) R273.2(P2) R277.2(P2) U15.59(BCBUS7)
N13955205: R271.2(P2) U15.32(ACBUS5)
N13955370: U16.4(Y) U17.1(1A)
N13955506: R532.1(P1) R687.2(P2) R718.2(P2) U17.6(1Y)
N14047716: C183.1 R328.1(P1)
N14047771: C184.1 R329.1(P1)
N14047989: C185.1 R337.1(P1)
N14048001: C187.1 R338.1(P1)
N14133978: U15.63(EECS) U18.1(CS)
N14133990: U15.62(EESK) U18.2(CLK)
N14134002: R276.1(P1) U15.61(EEDATA) U18.3(DI)
N14134094: R276.2(P2) R278.1(P1) U18.4(DO)
N14134760: R267.1(P1) U15.6(REF)
N14153033: R268.2(P2) U15.28(ACBUS2)
N14153037: R268.1(P1) R673.2(P2) U64.6(B2)
N14153103: R668.2(P2) U13.3(EN)
N14153116: C148.1 U13.4(NR)
N14153842: R270.1(P1) U15.14(RESET#)
N15558597: R289.2(P2) U43.23(ENR) U44.4(Y)
N15559775: C342.1 D14.3(CATHANOD)
N15733151: J45.5 R513.2(P2)
N15733155: J45.4 R514.2(P2)
N15733159: J45.3 R515.2(P2) R683.1(P1)
N16417304: R320.1(P1) R530.1(P1)
N17104819: R330.2(P2) Y5.1(OE)
N17425840: R562.1(P1) U46.72(CI2CA)
N17426045: U46.38(MCLK) U69.10(2B2)
N17426048: U46.45(SCK) U69.13(1B1)
N17426051: U46.41(SD0) U69.11(2B1)
N17426054: U46.44(WS) U69.12(1B2)
N17426077: R568.2(P2) U46.36(SPDIF)
N17426216: R573.2(P2) U46.69(IO_SEL)
N17426279: D21.1(Cathode) R576.2(P2)
N17426324: R578.1(P1) TP54.1
N18821813: R265.1(P1) U65.2(A1)
N18821974: R269.1(P1) U65.3(A2)
N19108270: R331.2(P2) Y5.3(CLK)
N19529678: J45.6 R679.2(P2) U67.4(Y)

Not connected (* = marked no-connect by the designer): J12 4(ID)*; J17 10(P10)*; J18 10(P10)*; J32 14(NC)*; J44 45* 49* 50*; J45 1* 2*; R323 2(P2)*; R324 1(P1)*; U14 2(NC)*; U15 22(ADBUS5)* 24(ADBUS7)* 27(ACBUS1)* 29(ACBUS3)* 33(ACBUS6)* 34(ACBUS7)* 36(SUSPEND#) 43(BDBUS4)* 44(BDBUS5)* 45(BDBUS6)* 46(BDBUS7)* 48(BCBUS0) 52(BCBUS1) 53(BCBUS2) 54(BCBUS3) 55(BCBUS4) 57(BCBUS5) 58(BCBUS6); U17 4(2Y)*; U42 4(NR)*; U43 14(C2+)*; U44 1(NC)*; U45 C1(2Y2)* C2(2Y1)* C5(2A1)* C6(2A2)* D1(2Y4)* D2(2Y3)* D5(2A3)* D6(2A4)*; U46 37(SD3)* 39(SD2)* 40(SD1)*; U48 C1(2Y2)* C2(2Y1)* C5(2A1)* C6(2A2)* D1(2Y4)* D2(2Y3)* D5(2A3)* D6(2A4)*; U66 1(NC)*; U67 1(NC)*; U70 1(~{OE})*

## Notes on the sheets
sheet 2
- Right Speaker
- Audio Codec
- Left Speaker
- Headphone
  Output
- Microphone
  Input
sheet 4
- Capacitive Touch Controller
- LCD Power
- BackLight Power
sheet 5
- HDMI Interface
sheet 7
- Camera Interface
sheet 8
- USB JTAG
- USB JTAG Power
